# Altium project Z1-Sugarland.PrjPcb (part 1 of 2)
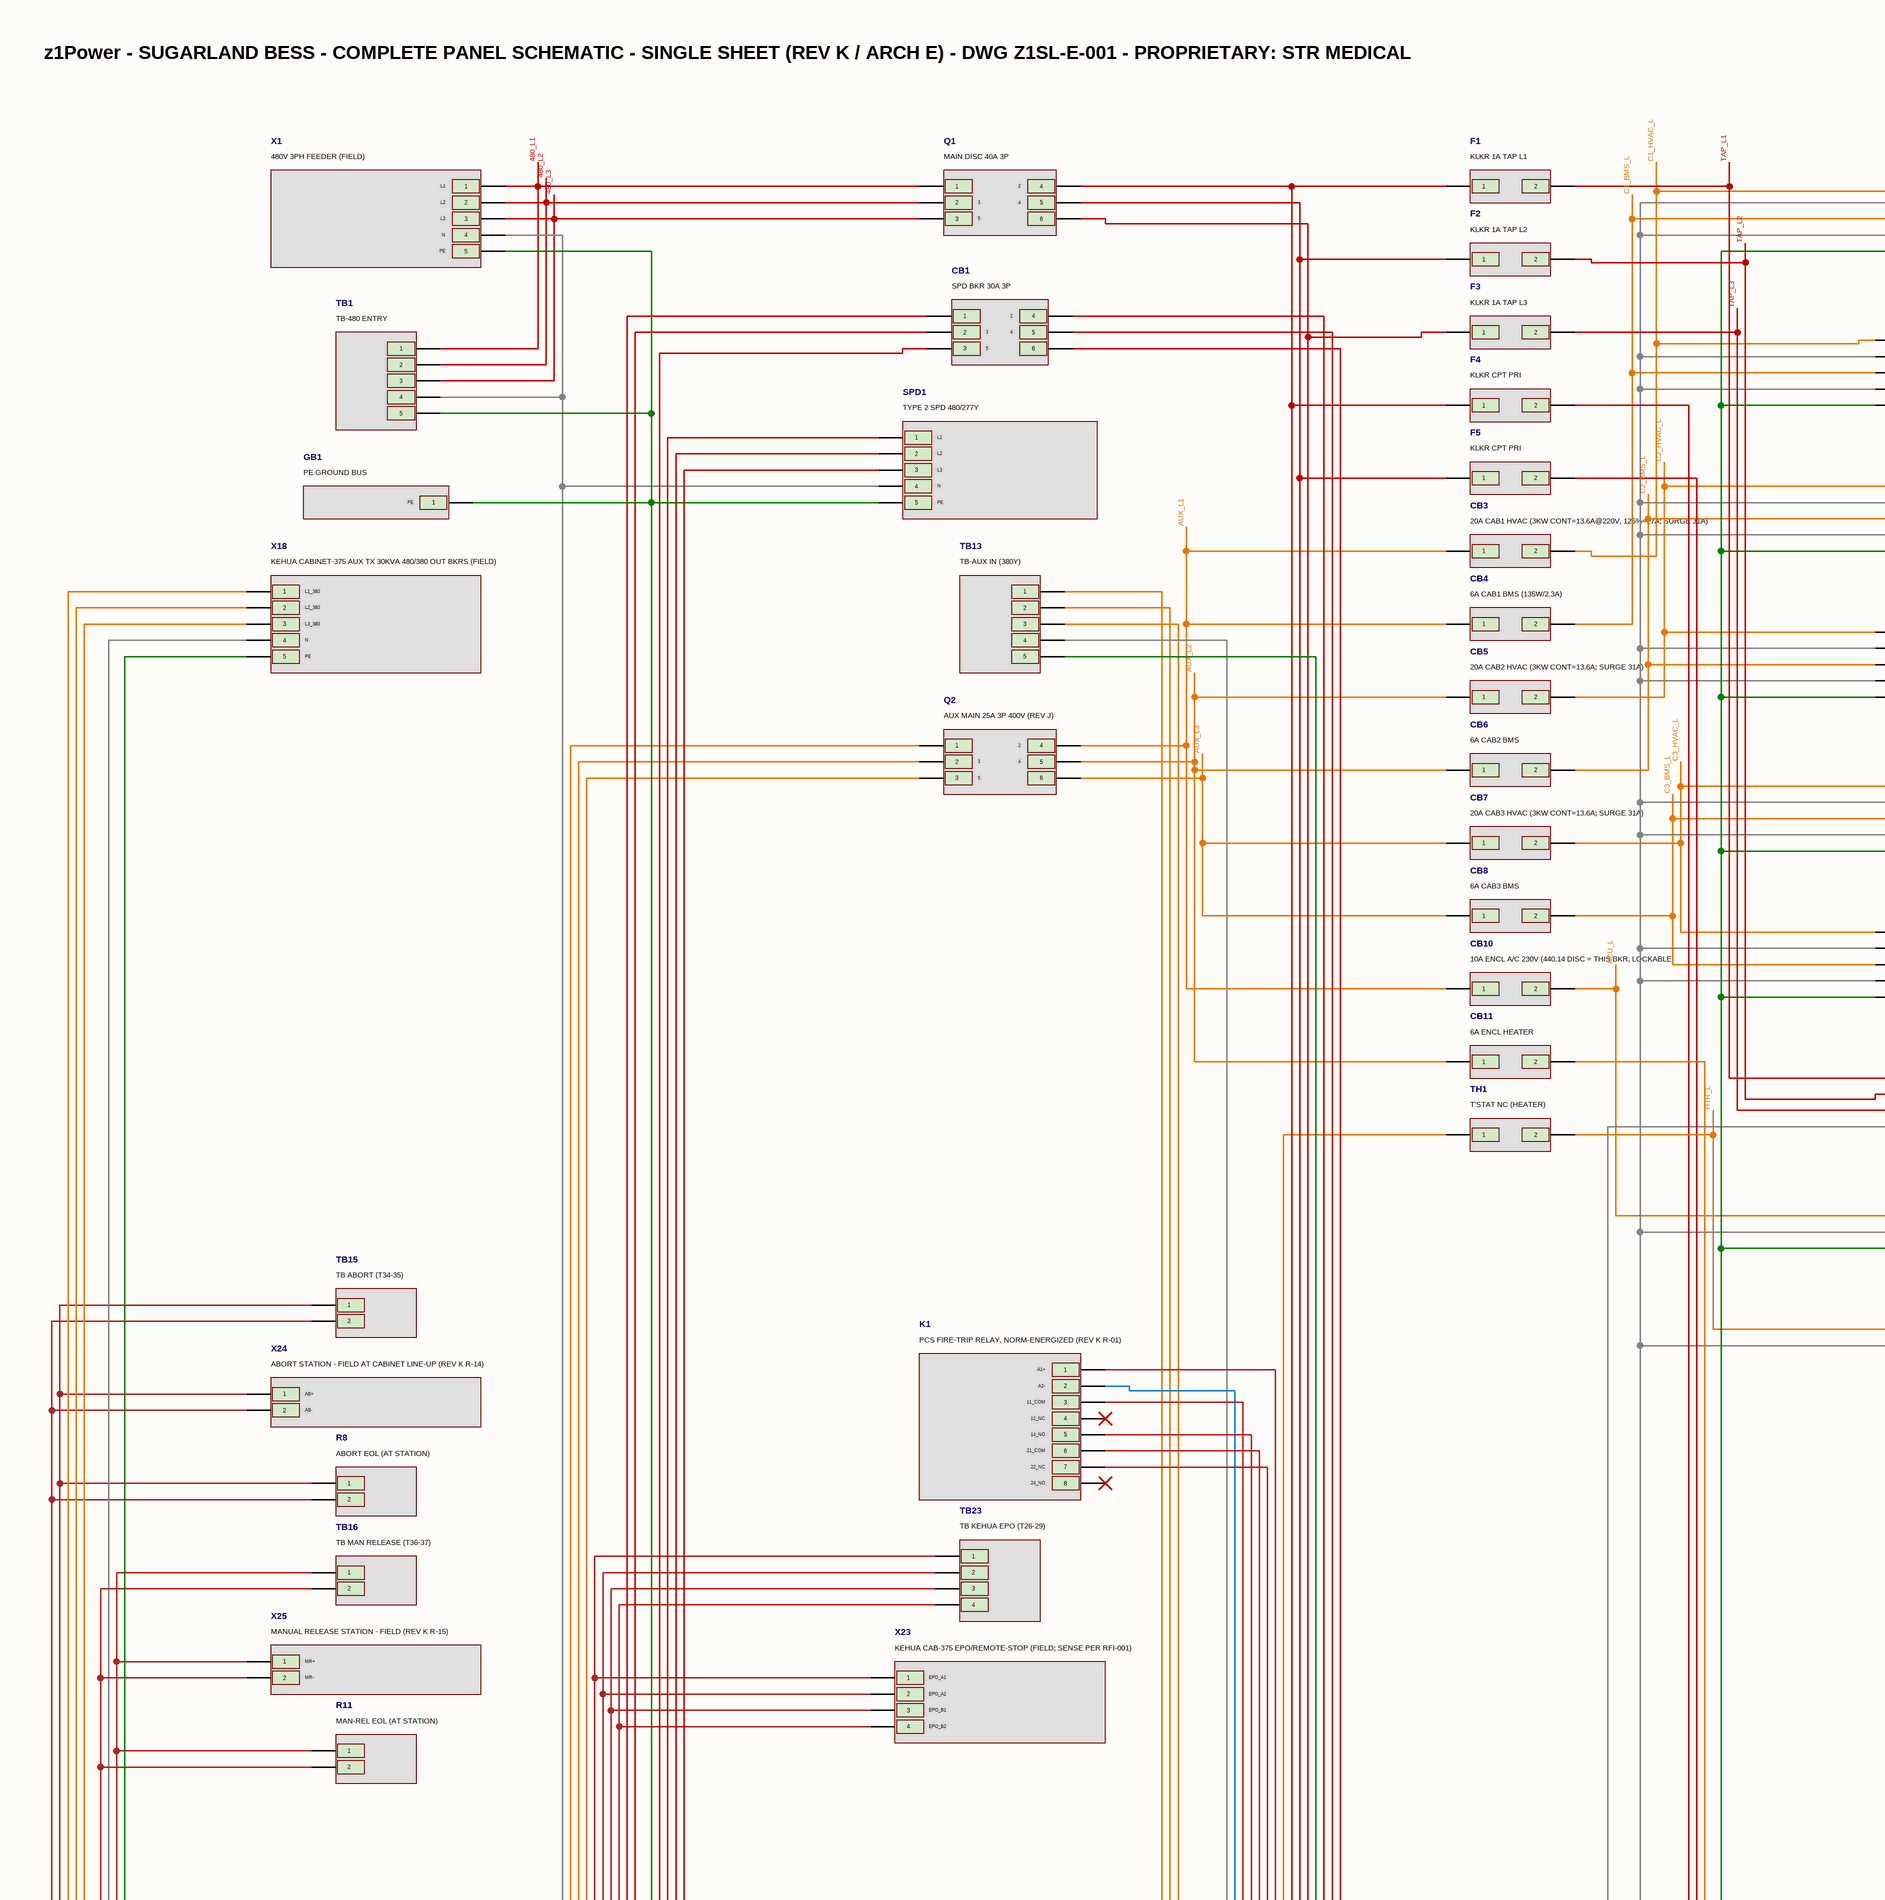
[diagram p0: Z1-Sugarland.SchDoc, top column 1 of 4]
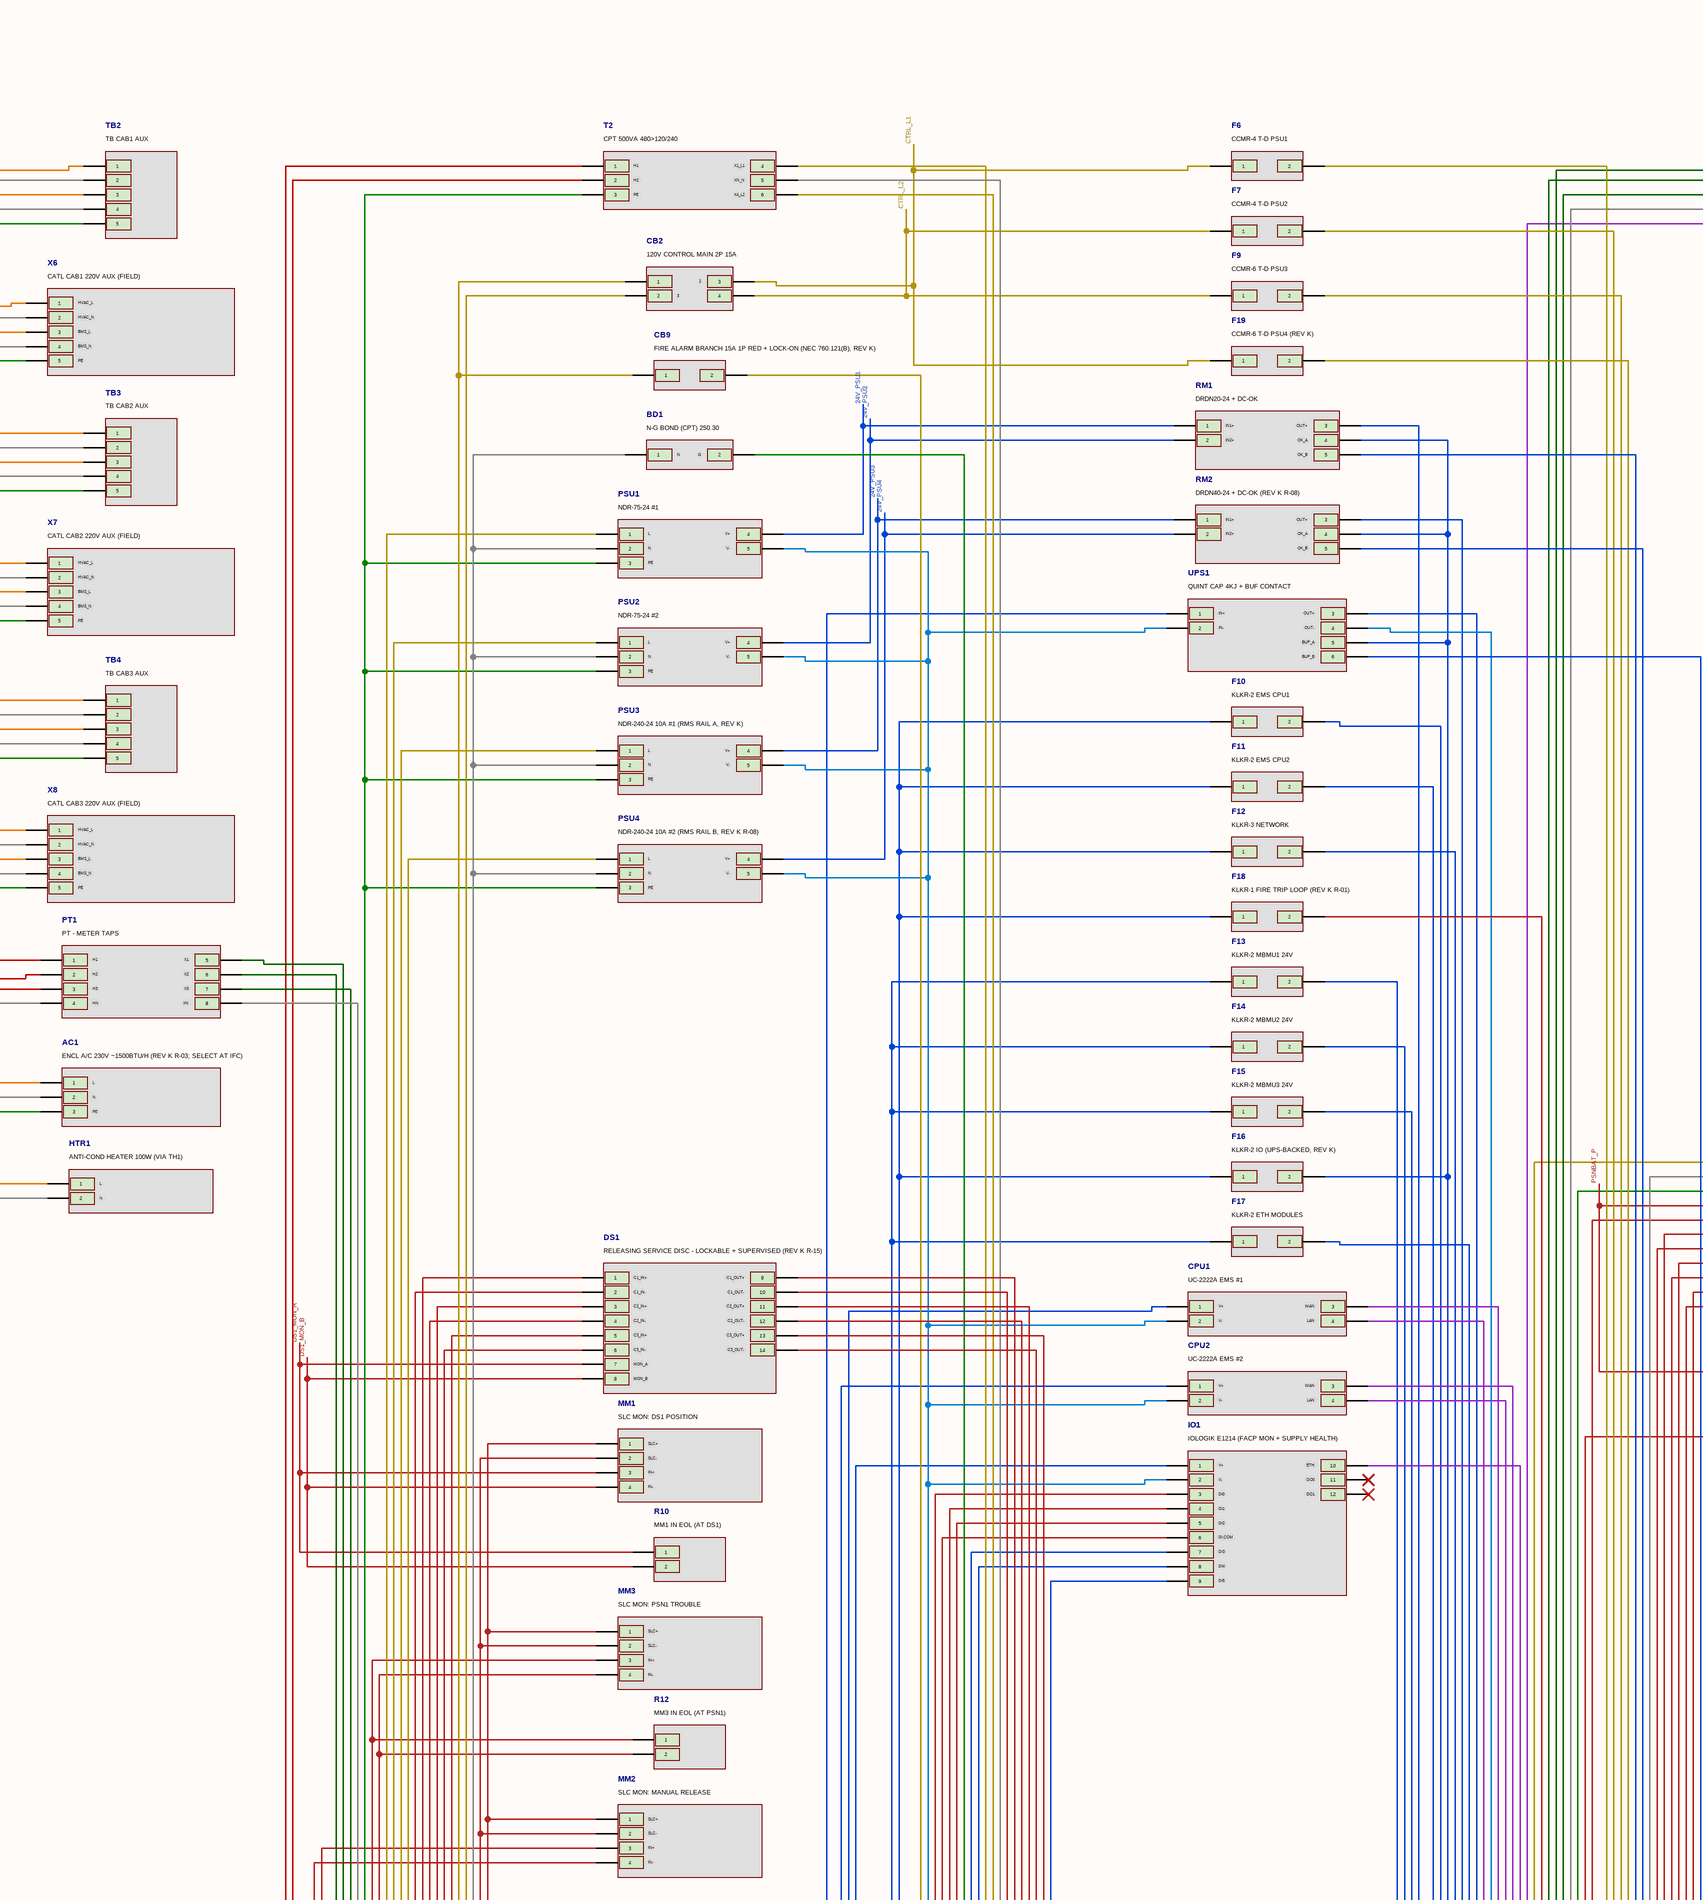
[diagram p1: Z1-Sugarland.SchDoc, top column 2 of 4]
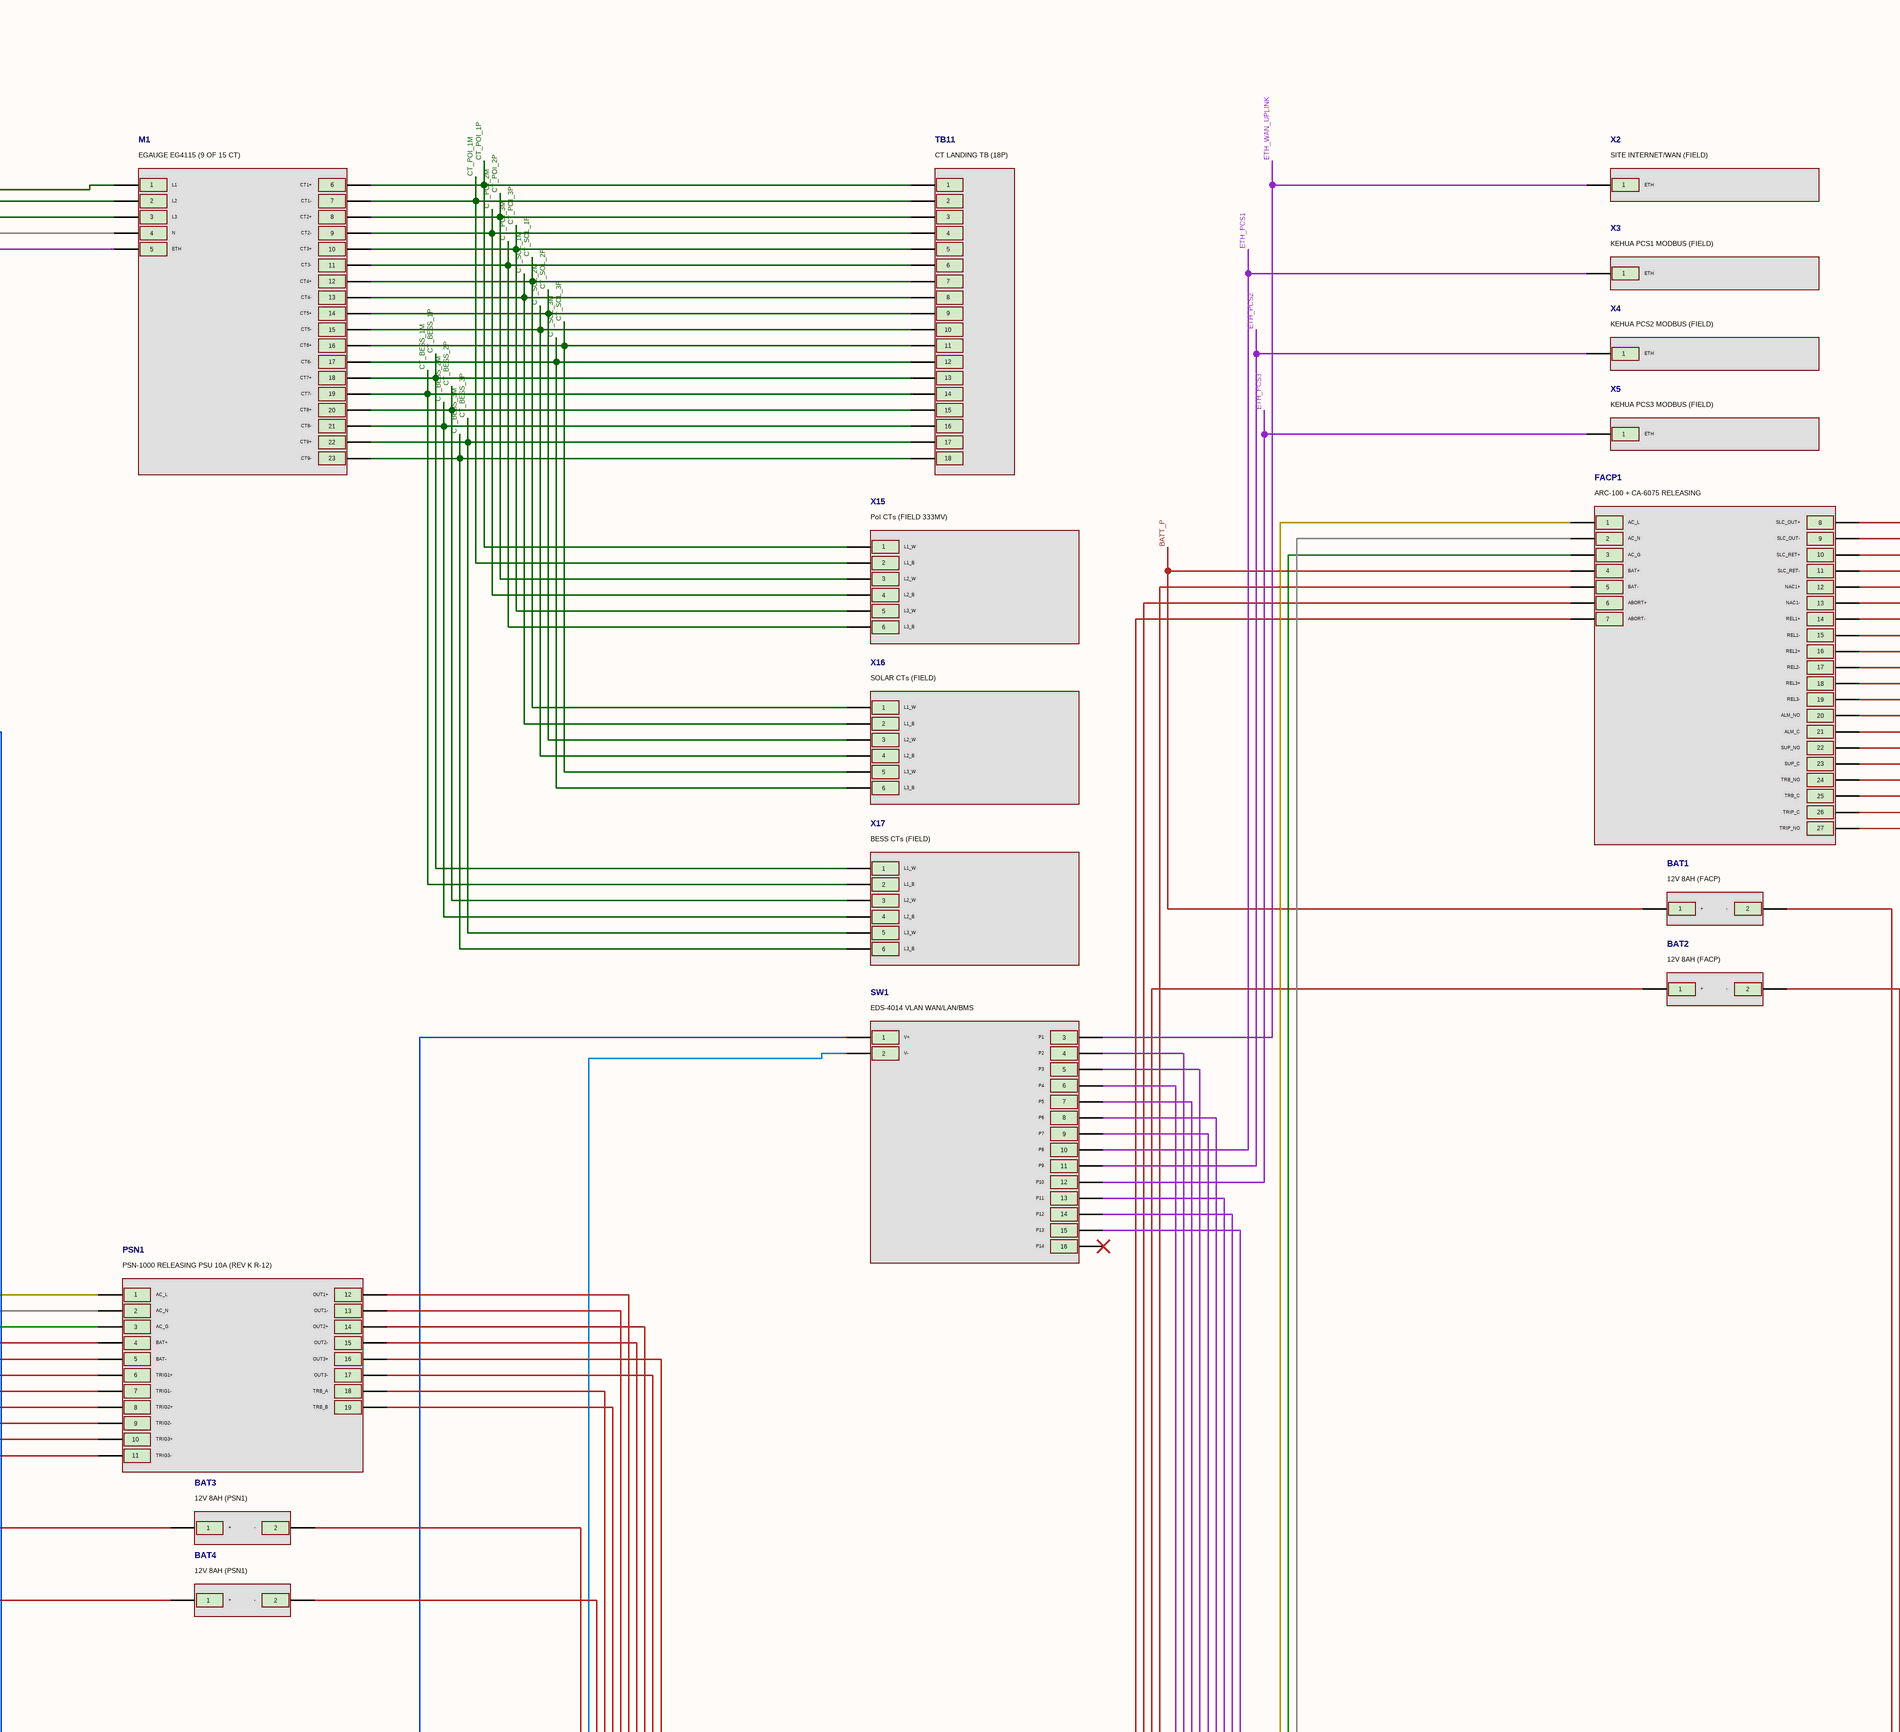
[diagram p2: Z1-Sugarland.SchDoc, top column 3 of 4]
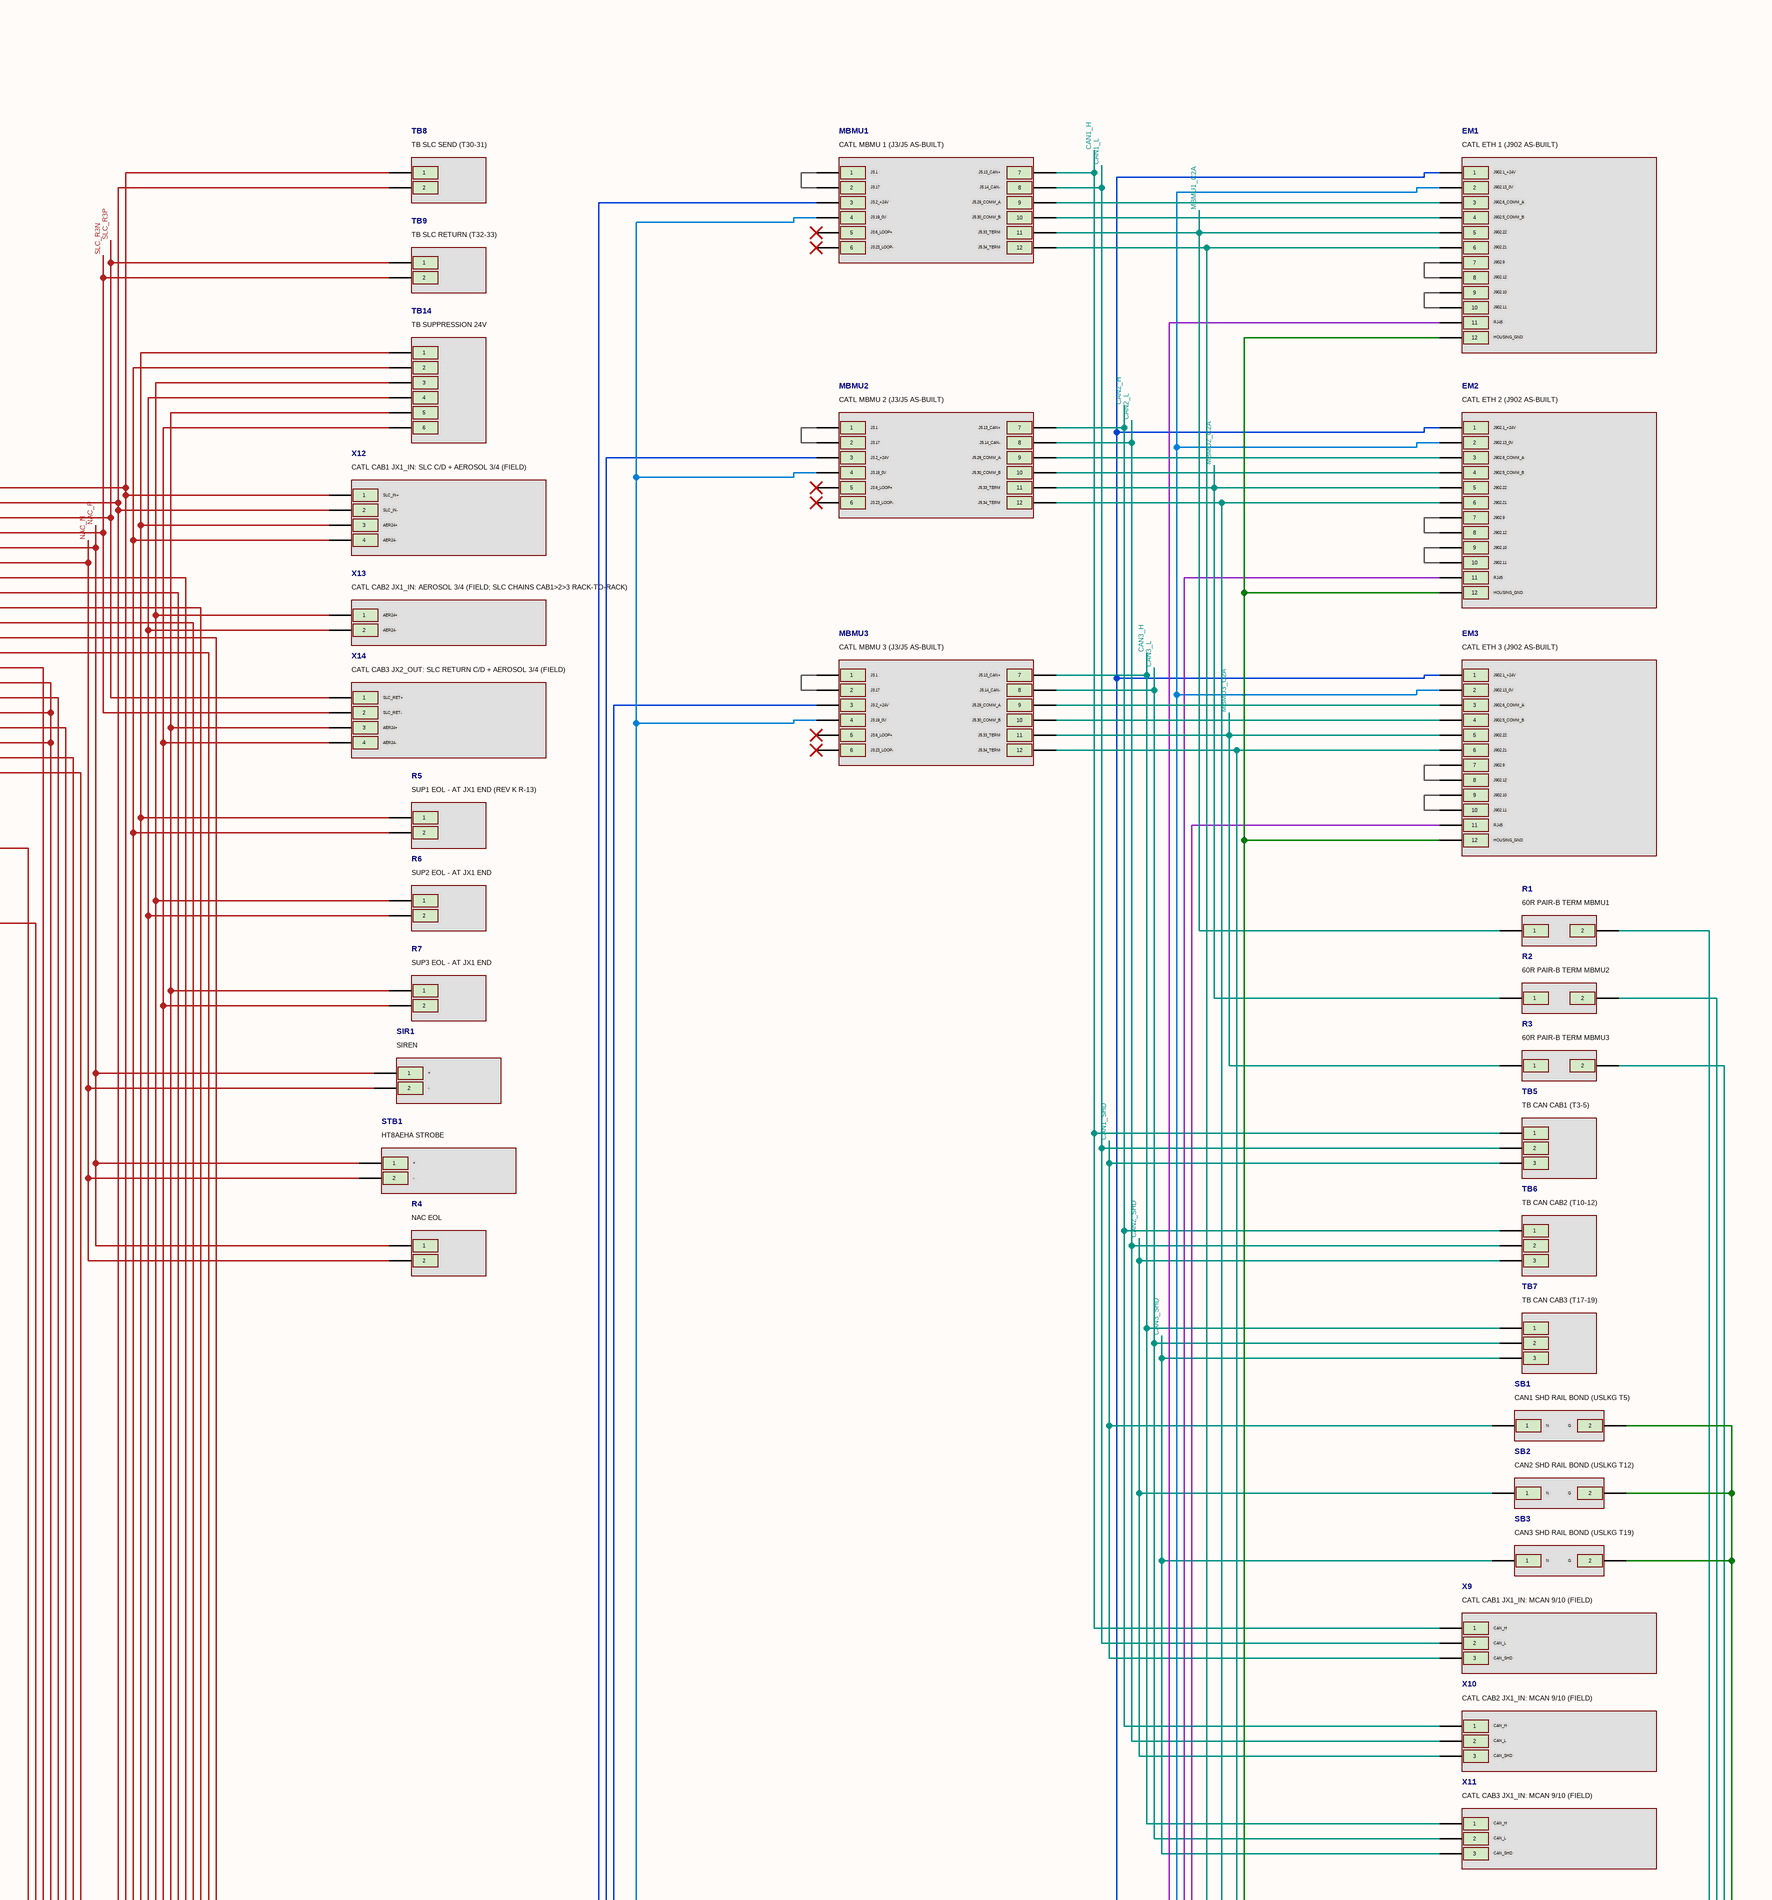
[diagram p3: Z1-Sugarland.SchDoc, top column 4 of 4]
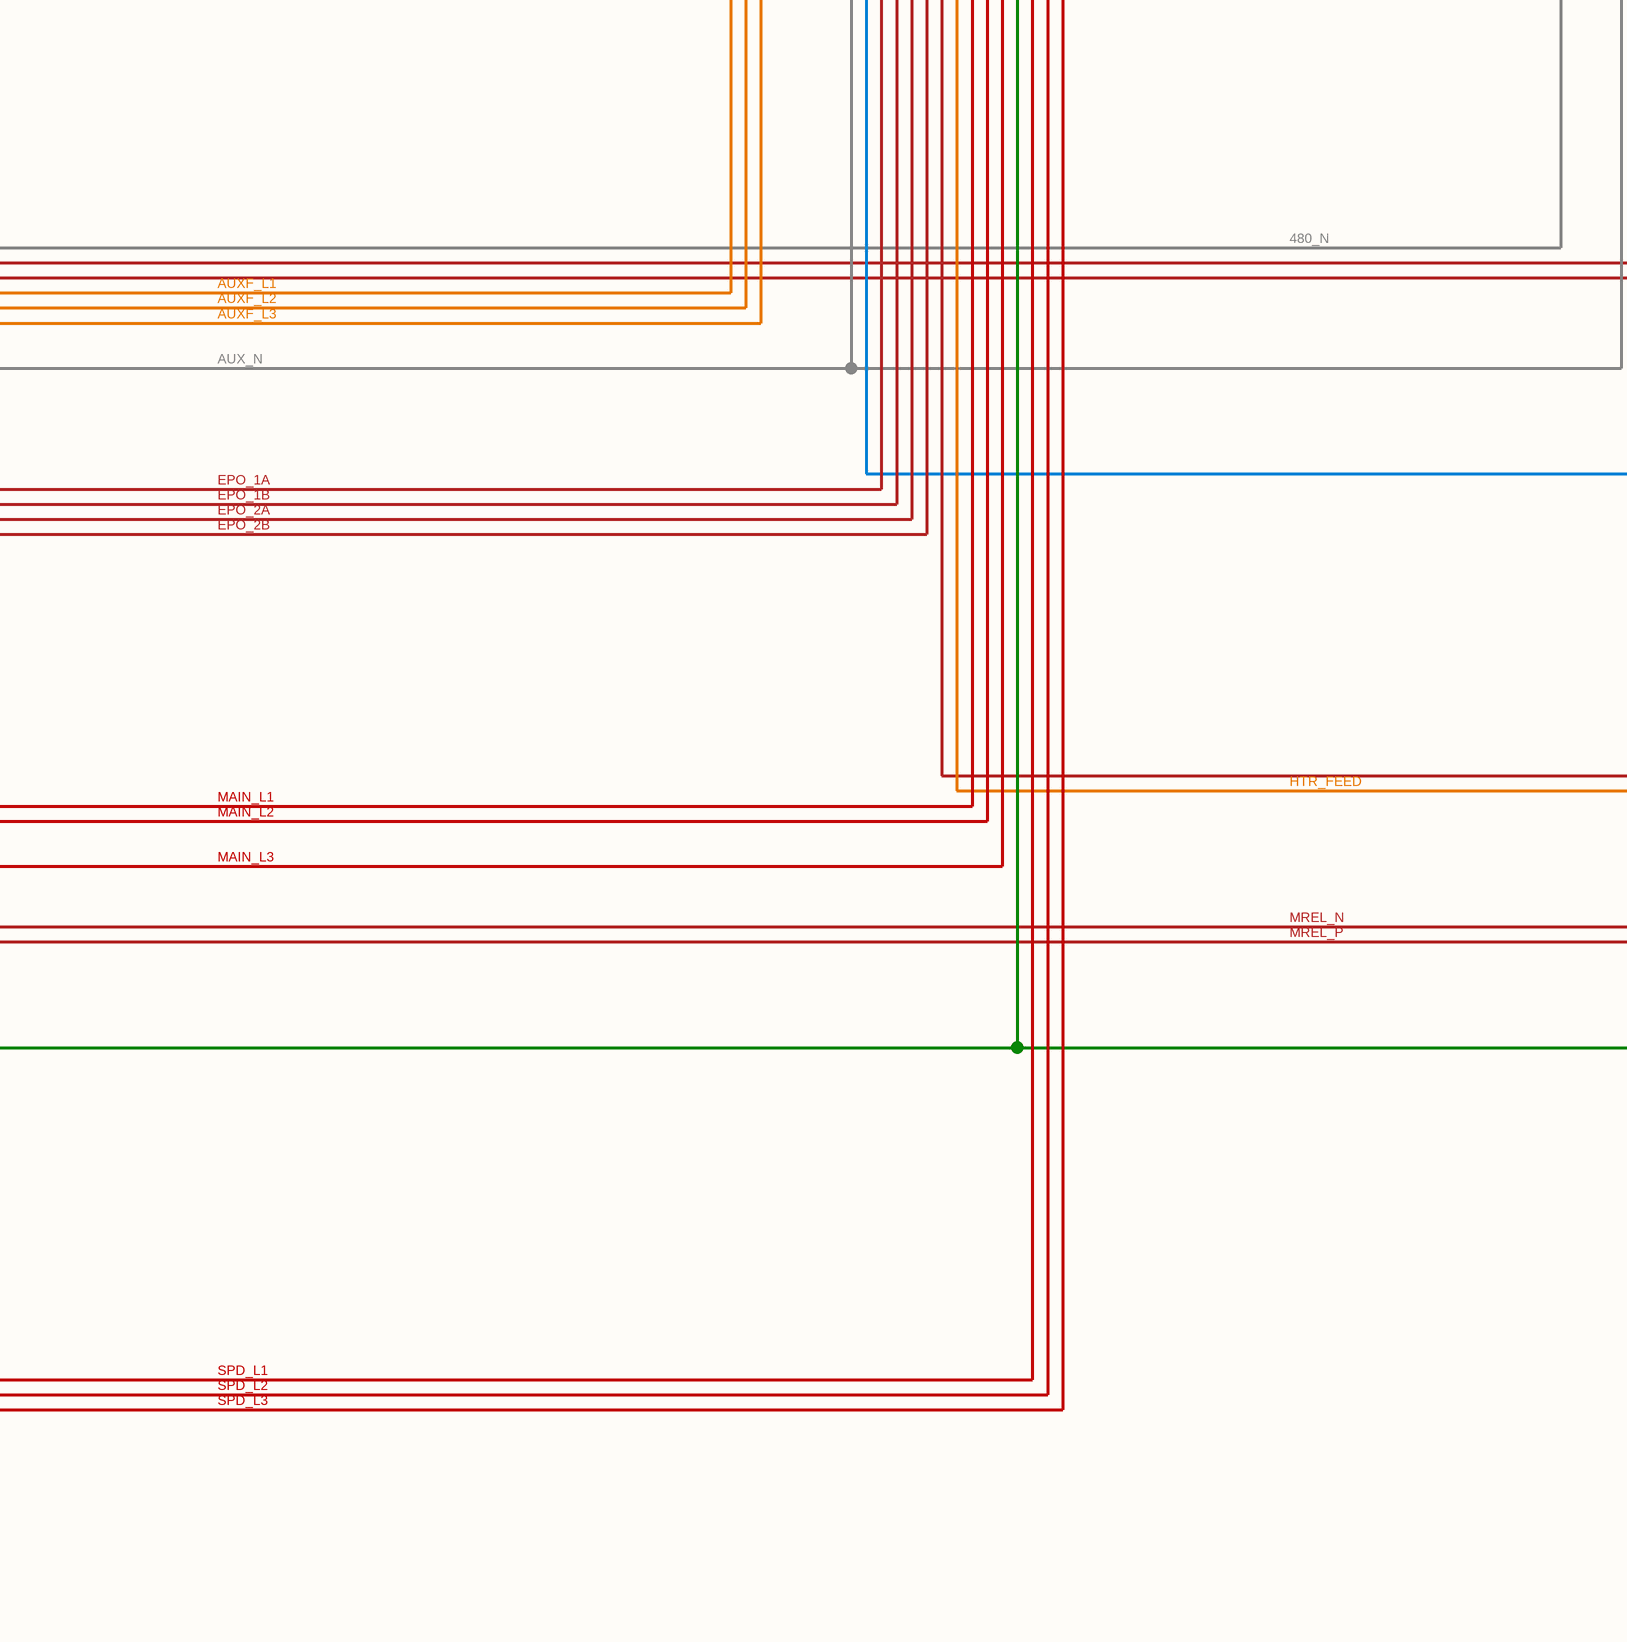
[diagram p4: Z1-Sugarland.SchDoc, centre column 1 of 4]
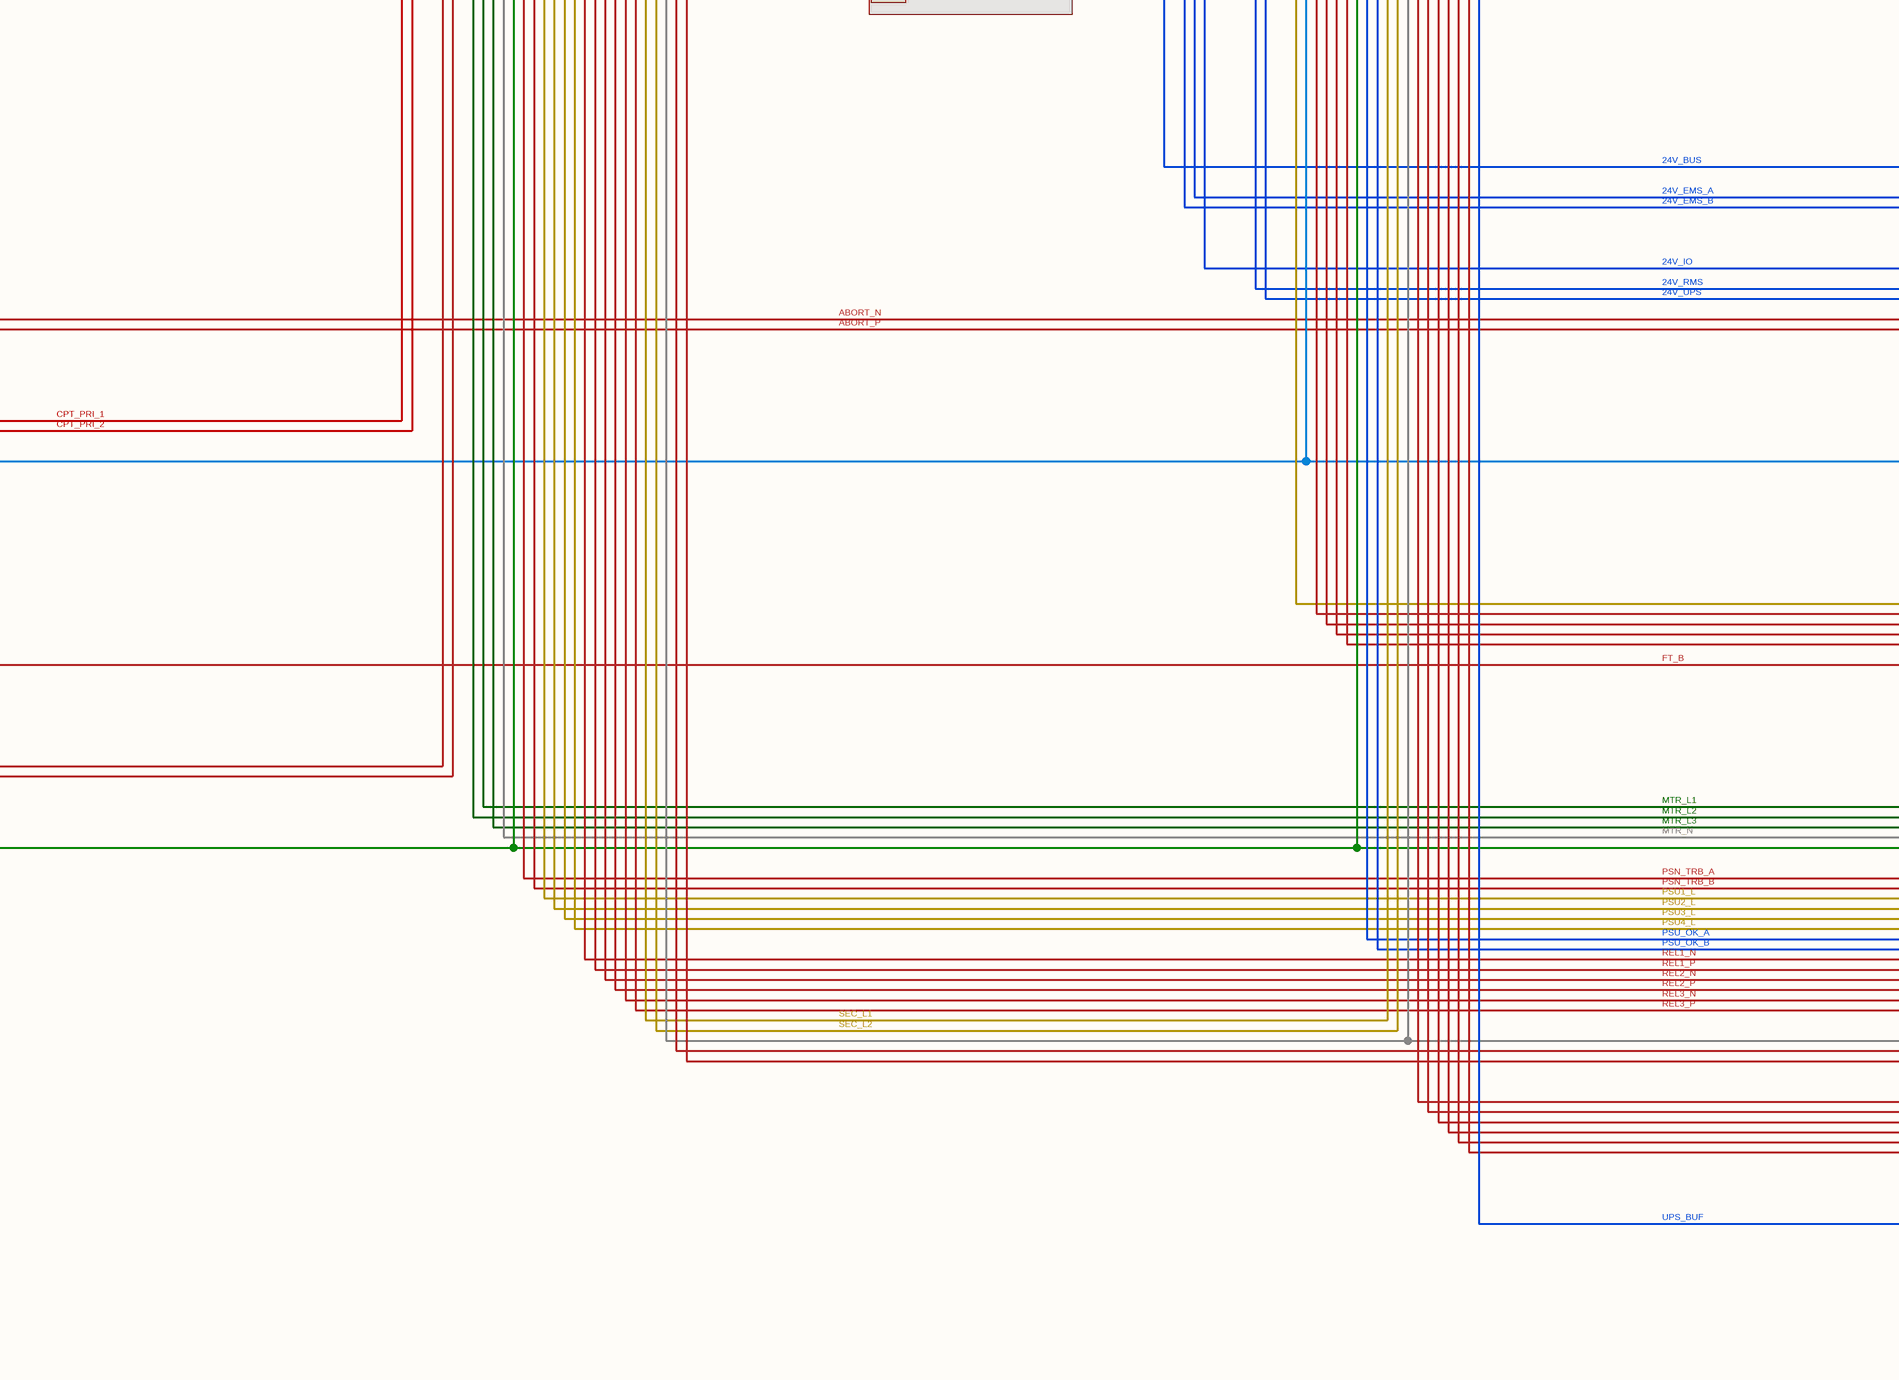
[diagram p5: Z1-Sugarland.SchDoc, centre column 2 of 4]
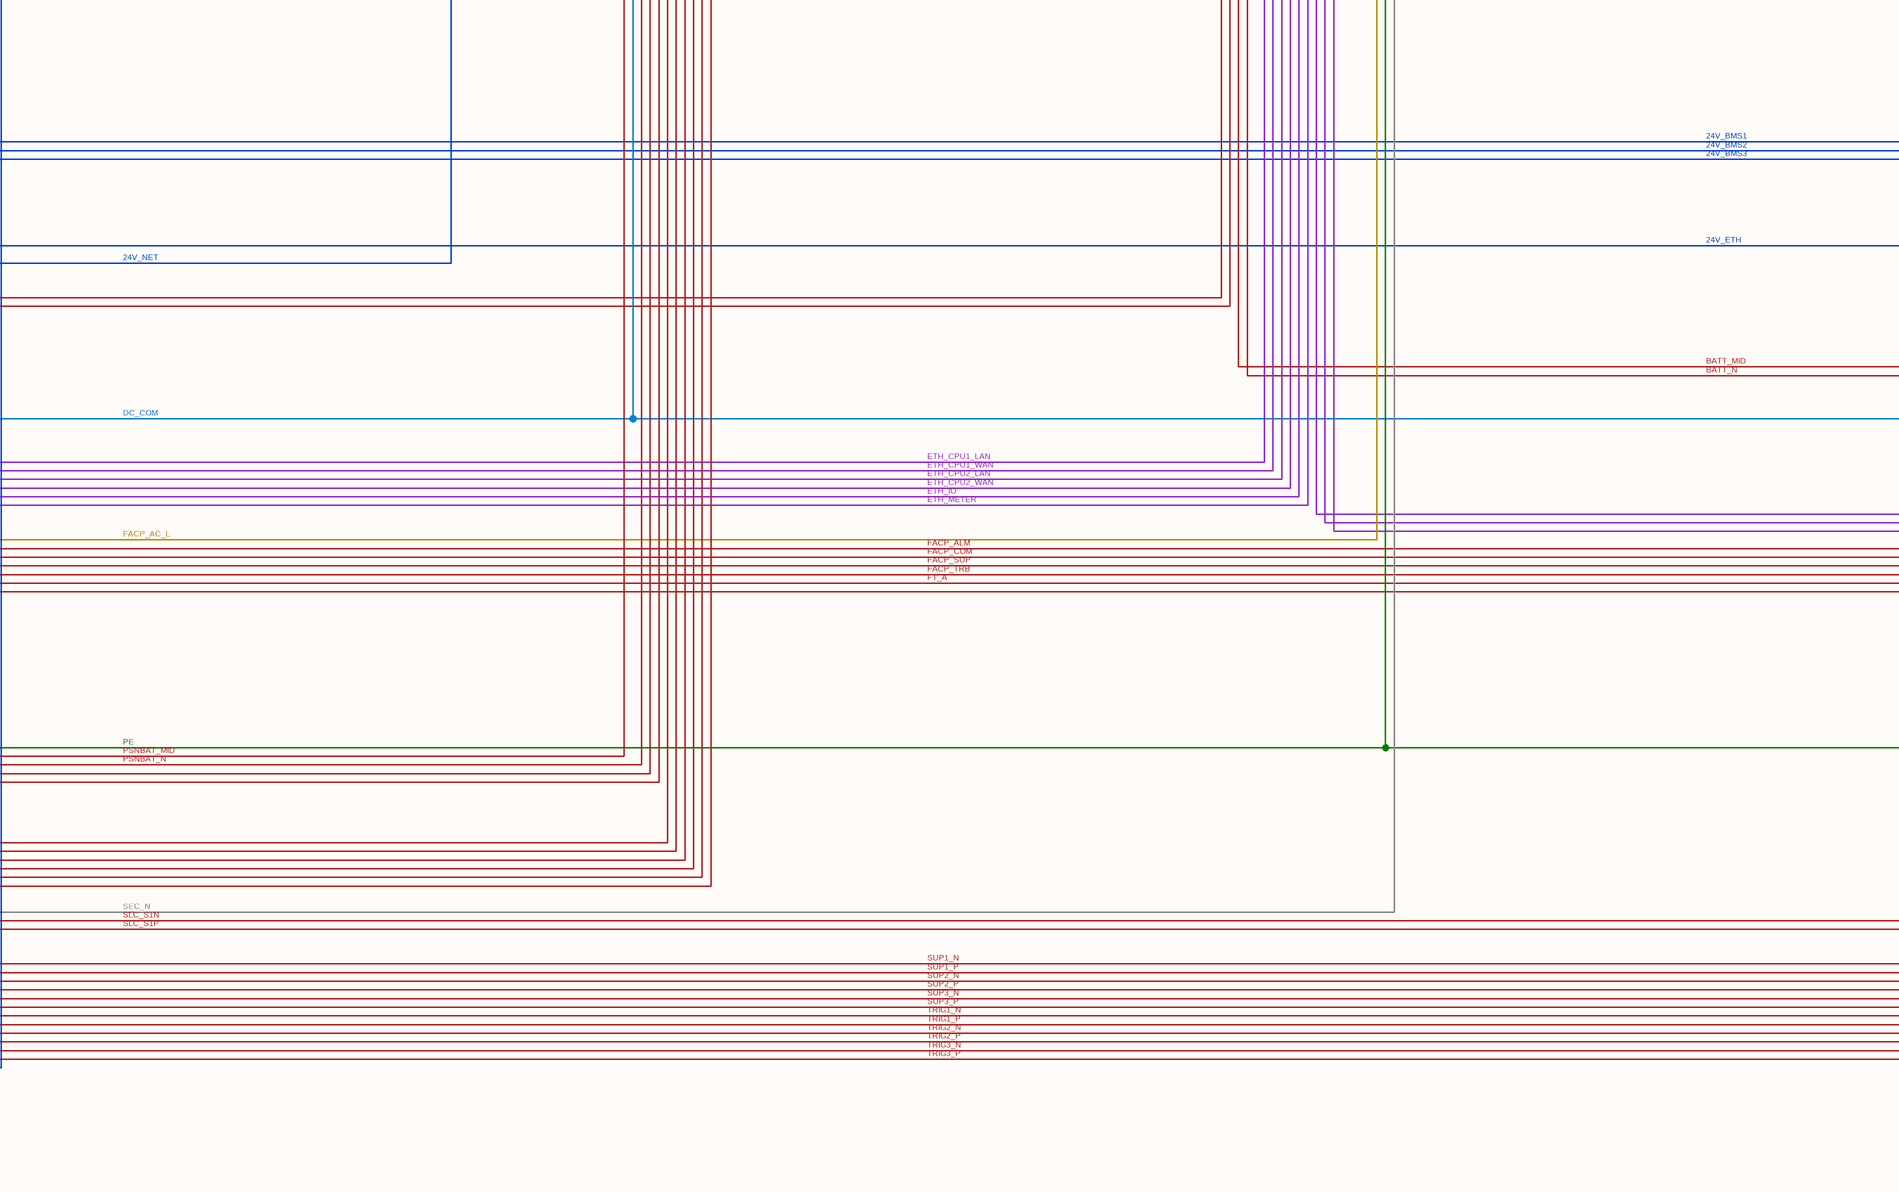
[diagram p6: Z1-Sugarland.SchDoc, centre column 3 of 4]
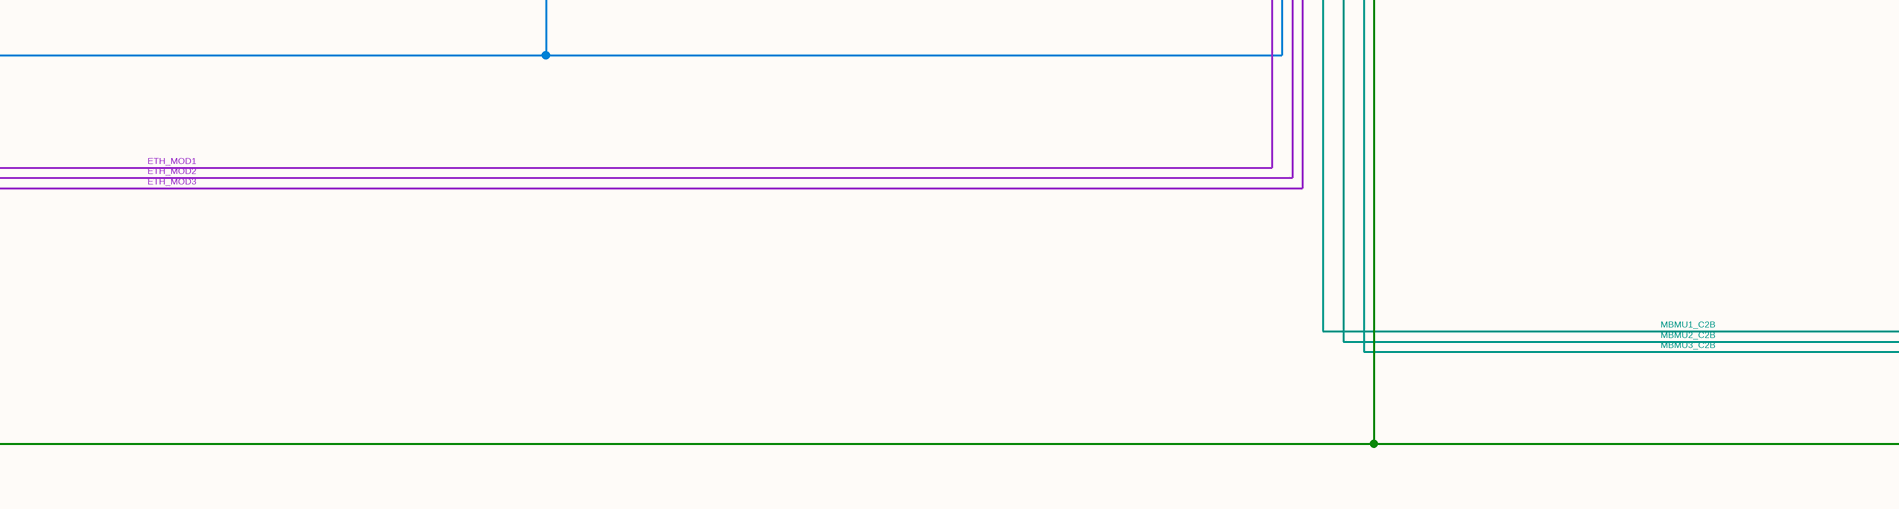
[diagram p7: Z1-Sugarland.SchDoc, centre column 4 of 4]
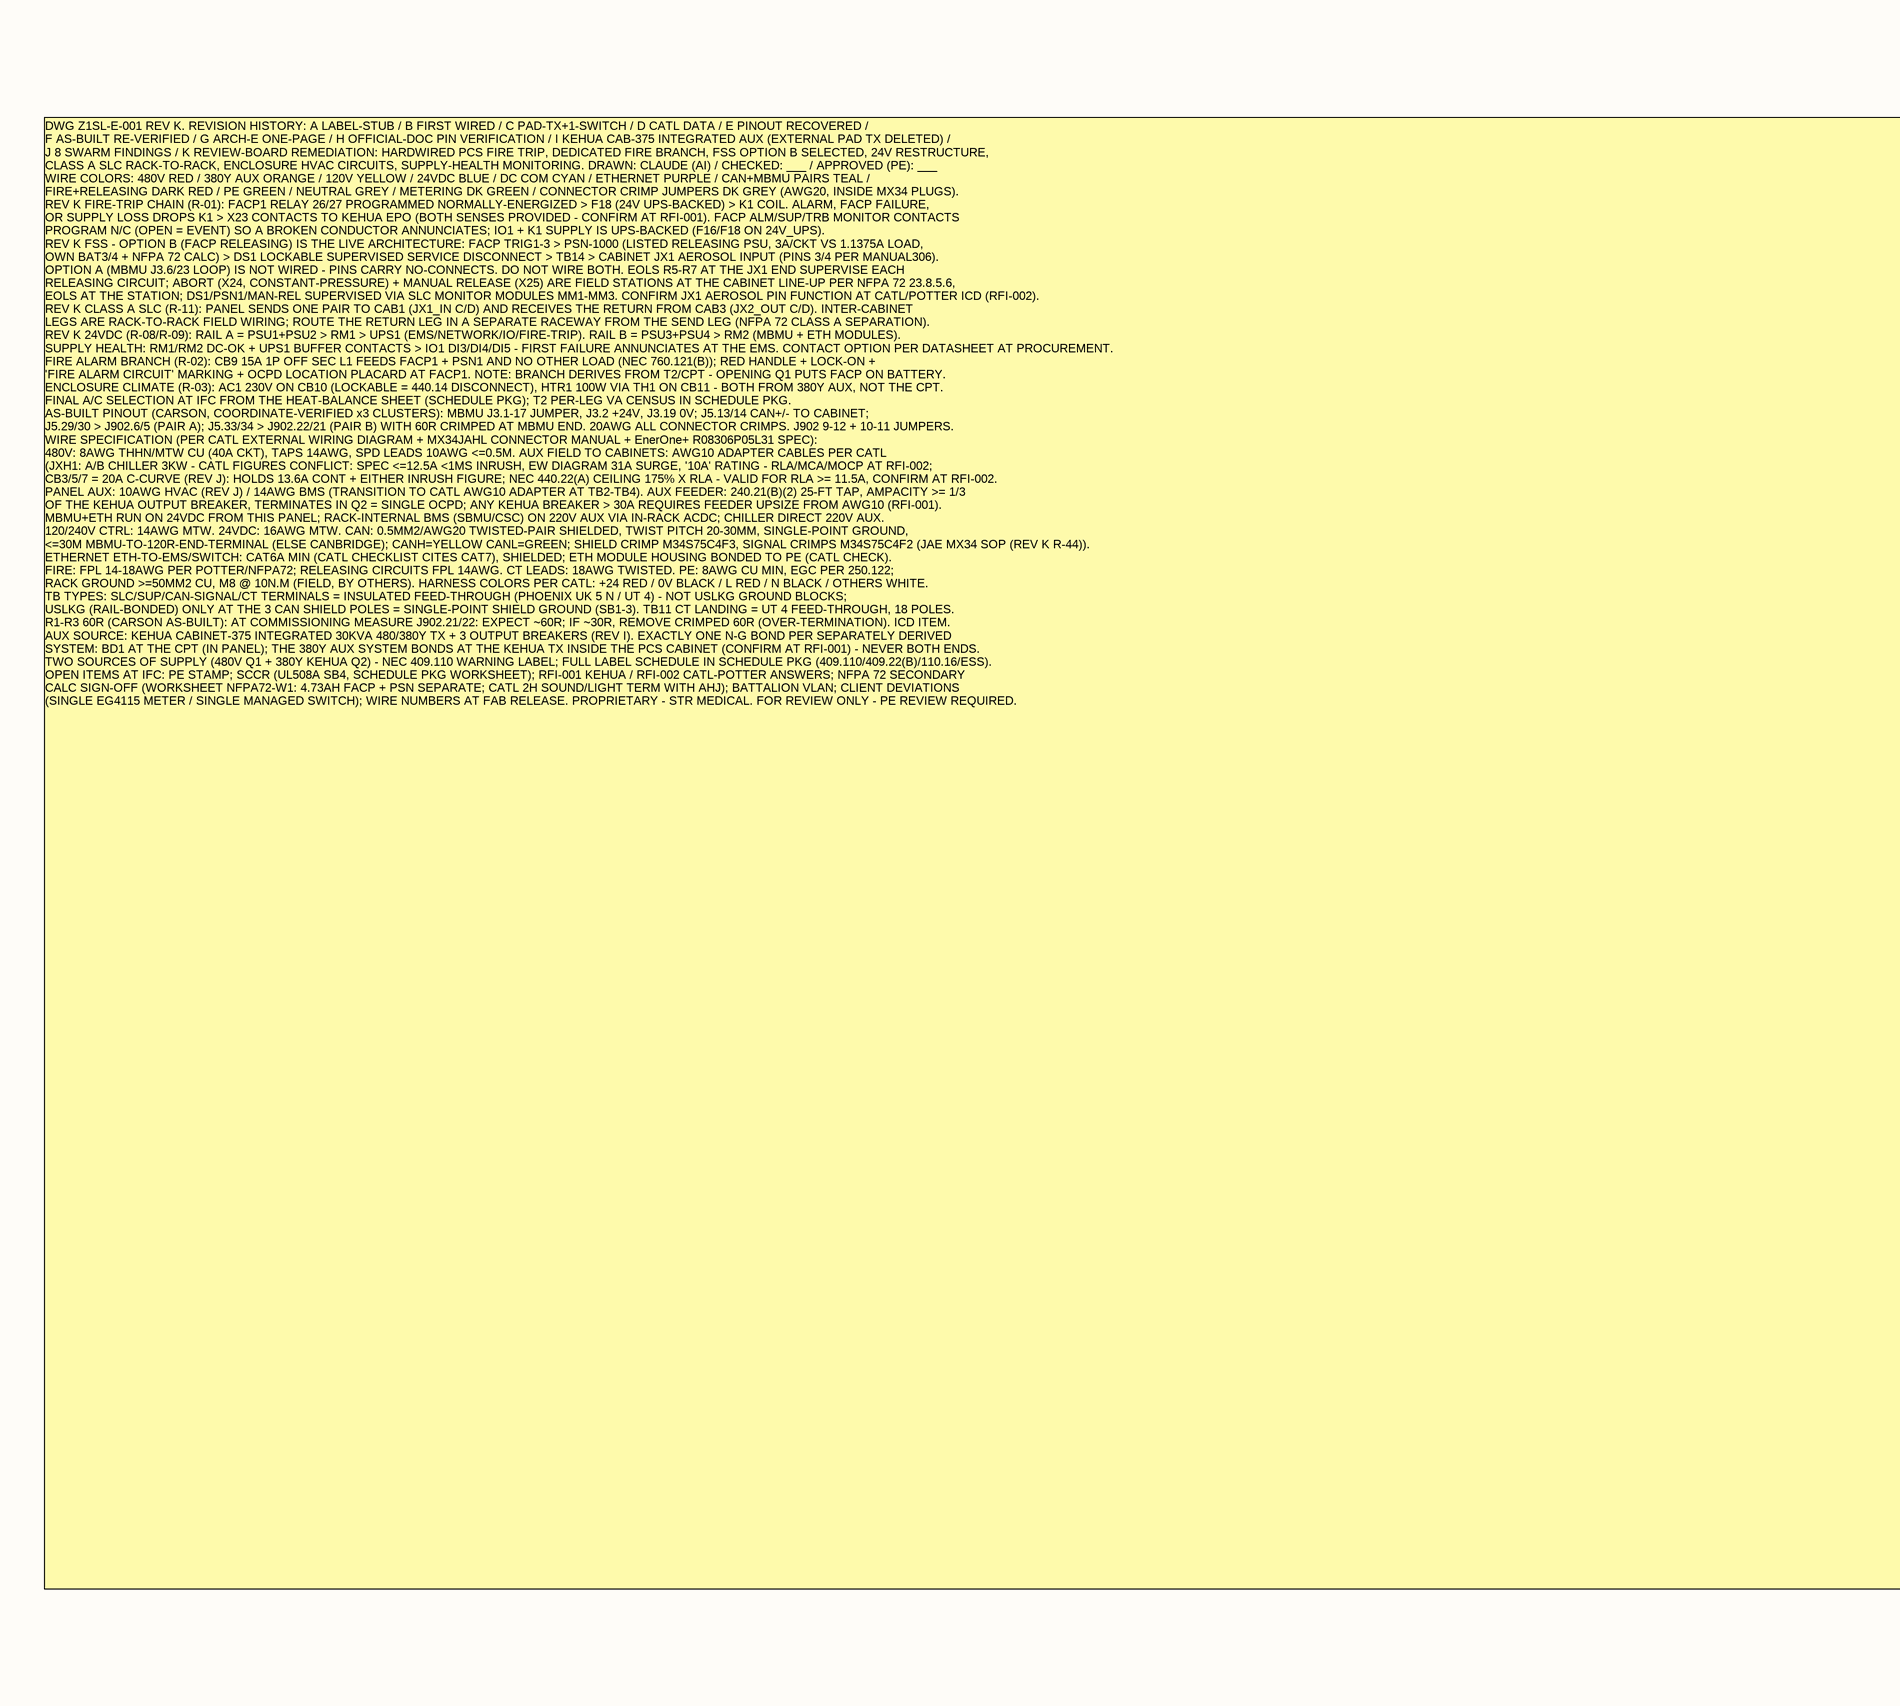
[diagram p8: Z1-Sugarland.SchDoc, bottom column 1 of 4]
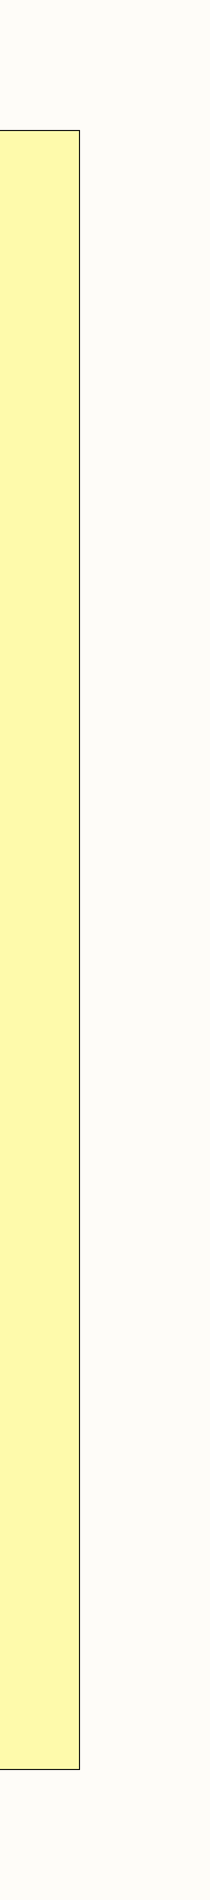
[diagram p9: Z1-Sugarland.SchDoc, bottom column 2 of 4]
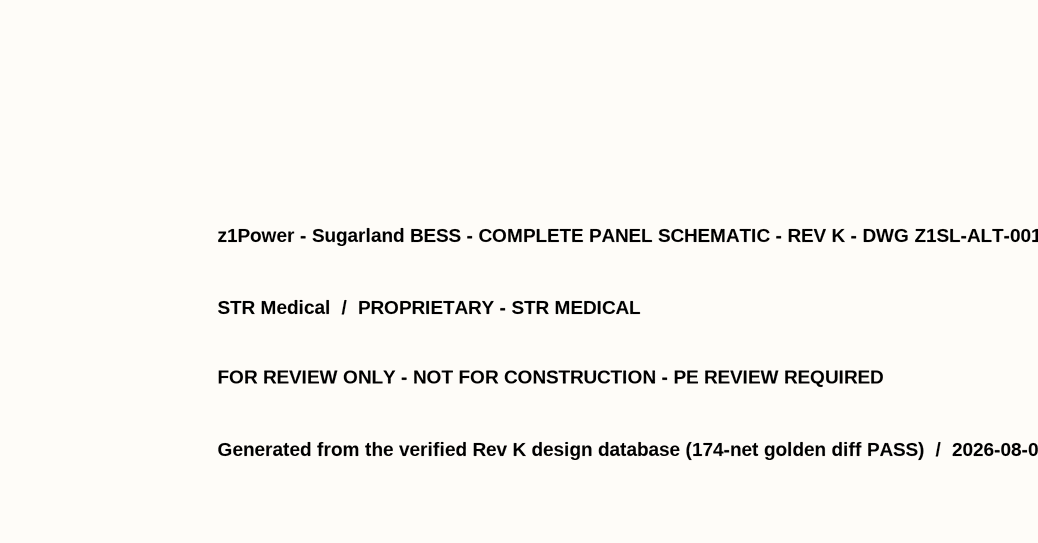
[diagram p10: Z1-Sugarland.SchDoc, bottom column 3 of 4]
2 sheets, 240 parts. Net scope: global (net labels, ports and power ports of the same name join across sheets).
Sheets:
  Z1-Sugarland.SchDoc
  Z1-Sugarland-Simplified.SchDoc

## Sheet Z1-Sugarland.SchDoc
size 1219 x 914 mm

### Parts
(Parts that share a designator on the sheet are numbered #1, #2 ... from top to bottom, then left to right.)
AC1#1  ENCL A/C 230V ~1500BTU/H (REV K R-03; SELECT AT IFC)
BAT1#1  12V 8AH (FACP)
BAT2#1  12V 8AH (FACP)
BAT3#1  12V 8AH (PSN1)
BAT4#1  12V 8AH (PSN1)
BD1#1  N-G BOND (CPT) 250.30
CB1#1  SPD BKR 30A 3P
CB2#1  120V CONTROL MAIN 2P 15A
CB3#1  20A CAB1 HVAC (3KW CONT=13.6A@220V, 125%=17A; SURGE 31A)
CB4#1  6A CAB1 BMS (135W/2.3A)
CB5#1  20A CAB2 HVAC (3KW CONT=13.6A; SURGE 31A)
CB6#1  6A CAB2 BMS
CB7#1  20A CAB3 HVAC (3KW CONT=13.6A; SURGE 31A)
CB8#1  6A CAB3 BMS
CB9#1  FIRE ALARM BRANCH 15A 1P RED + LOCK-ON (NEC 760.121(B), REV K)
CB10#1  10A ENCL A/C 230V (440.14 DISC = THIS BKR, LOCKABLE)
CB11#1  6A ENCL HEATER
CPU1#1  UC-2222A EMS #1
CPU2#1  UC-2222A EMS #2
DS1#1  RELEASING SERVICE DISC - LOCKABLE + SUPERVISED (REV K R-15)
EM1#1  CATL ETH 1 (J902 AS-BUILT)
EM2#1  CATL ETH 2 (J902 AS-BUILT)
EM3#1  CATL ETH 3 (J902 AS-BUILT)
F1#1  KLKR 1A TAP L1
F2#1  KLKR 1A TAP L2
F3#1  KLKR 1A TAP L3
F4#1  KLKR CPT PRI
F5#1  KLKR CPT PRI
F6#1  CCMR-4 T-D PSU1
F7#1  CCMR-4 T-D PSU2
F9#1  CCMR-6 T-D PSU3
F10#1  KLKR-2 EMS CPU1
F11#1  KLKR-2 EMS CPU2
F12#1  KLKR-3 NETWORK
F13#1  KLKR-2 MBMU1 24V
F14#1  KLKR-2 MBMU2 24V
F15#1  KLKR-2 MBMU3 24V
F16#1  KLKR-2 IO (UPS-BACKED, REV K)
F17#1  KLKR-2 ETH MODULES
F18#1  KLKR-1 FIRE TRIP LOOP (REV K R-01)
F19#1  CCMR-6 T-D PSU4 (REV K)
FACP1#1  ARC-100 + CA-6075 RELEASING
GB1#1  PE GROUND BUS
HTR1#1  ANTI-COND HEATER 100W (VIA TH1)
IO1#1  IOLOGIK E1214 (FACP MON + SUPPLY HEALTH)
K1#1  PCS FIRE-TRIP RELAY, NORM-ENERGIZED (REV K R-01)
M1#1  EGAUGE EG4115 (9 OF 15 CT)
MBMU1#1  CATL MBMU 1 (J3/J5 AS-BUILT)
MBMU2#1  CATL MBMU 2 (J3/J5 AS-BUILT)
MBMU3#1  CATL MBMU 3 (J3/J5 AS-BUILT)
MM1#1  SLC MON: DS1 POSITION
MM2#1  SLC MON: MANUAL RELEASE
MM3#1  SLC MON: PSN1 TROUBLE
PSN1#1  PSN-1000 RELEASING PSU 10A (REV K R-12)
PSU1#1  NDR-75-24 #1
PSU2#1  NDR-75-24 #2
PSU3#1  NDR-240-24 10A #1 (RMS RAIL A, REV K)
PSU4#1  NDR-240-24 10A #2 (RMS RAIL B, REV K R-08)
PT1#1  PT - METER TAPS
Q1#1  MAIN DISC 40A 3P
Q2#1  AUX MAIN 25A 3P 400V (REV J)
R1#1  60R PAIR-B TERM MBMU1
R2#1  60R PAIR-B TERM MBMU2
R3#1  60R PAIR-B TERM MBMU3
R4#1  NAC EOL
R5#1  SUP1 EOL - AT JX1 END (REV K R-13)
R6#1  SUP2 EOL - AT JX1 END
R7#1  SUP3 EOL - AT JX1 END
R8#1  ABORT EOL (AT STATION)
R10#1  MM1 IN EOL (AT DS1)
R11#1  MAN-REL EOL (AT STATION)
R12#1  MM3 IN EOL (AT PSN1)
RM1#1  DRDN20-24 + DC-OK
RM2#1  DRDN40-24 + DC-OK (REV K R-08)
SB1#1  CAN1 SHD RAIL BOND (USLKG T5)
SB2#1  CAN2 SHD RAIL BOND (USLKG T12)
SB3#1  CAN3 SHD RAIL BOND (USLKG T19)
SIR1#1  SIREN
SPD1#1  TYPE 2 SPD 480/277Y
STB1#1  HT8AEHA STROBE
SW1#1  EDS-4014 VLAN WAN/LAN/BMS
T2#1  CPT 500VA 480>120/240
TB1#1  TB-480 ENTRY
TB2#1  TB CAB1 AUX
TB3#1  TB CAB2 AUX
TB4#1  TB CAB3 AUX
TB5#1  TB CAN CAB1 (T3-5)
TB6#1  TB CAN CAB2 (T10-12)
TB7#1  TB CAN CAB3 (T17-19)
TB8#1  TB SLC SEND (T30-31)
TB9#1  TB SLC RETURN (T32-33)
TB11#1  CT LANDING TB (18P)
TB13#1  TB-AUX IN (380Y)
TB14#1  TB SUPPRESSION 24V
TB15#1  TB ABORT (T34-35)
TB16#1  TB MAN RELEASE (T36-37)
TB23#1  TB KEHUA EPO (T26-29)
TH1#1  T'STAT NC (HEATER)
UPS1#1  QUINT CAP 4KJ + BUF CONTACT
X1#1  480V 3PH FEEDER (FIELD)
X2#1  SITE INTERNET/WAN (FIELD)
X3#1  KEHUA PCS1 MODBUS (FIELD)
X4#1  KEHUA PCS2 MODBUS (FIELD)
X5#1  KEHUA PCS3 MODBUS (FIELD)
X6#1  CATL CAB1 220V AUX (FIELD)
X7#1  CATL CAB2 220V AUX (FIELD)
X8#1  CATL CAB3 220V AUX (FIELD)
X9#1  CATL CAB1 JX1_IN: MCAN 9/10 (FIELD)
X10#1  CATL CAB2 JX1_IN: MCAN 9/10 (FIELD)
X11#1  CATL CAB3 JX1_IN: MCAN 9/10 (FIELD)
X12#1  CATL CAB1 JX1_IN: SLC C/D + AEROSOL 3/4 (FIELD)
X13#1  CATL CAB2 JX1_IN: AEROSOL 3/4 (FIELD; SLC CHAINS CAB1>2>3 RACK-TO-RACK)
X14#1  CATL CAB3 JX2_OUT: SLC RETURN C/D + AEROSOL 3/4 (FIELD)
X15#1  PoI CTs (FIELD 333MV)
X16#1  SOLAR CTs (FIELD)
X17#1  BESS CTs (FIELD)
X18#1  KEHUA CABINET-375 AUX TX 30KVA 480/380 OUT BKRS (FIELD)
X23#1  KEHUA CAB-375 EPO/REMOTE-STOP (FIELD; SENSE PER RFI-001)
X24#1  ABORT STATION - FIELD AT CABINET LINE-UP (REV K R-14)
X25#1  MANUAL RELEASE STATION - FIELD (REV K R-15)

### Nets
24V_ETH: EM1#1.1(J902.1_+24V) EM2#1.1(J902.1_+24V) EM3#1.1(J902.1_+24V) F17#1.2
24V_RMS: F13#1.1 F14#1.1 F15#1.1 F17#1.1 RM2#1.3(OUT+)
24V_UPS: F10#1.1 F11#1.1 F12#1.1 F16#1.1 F18#1.1 UPS1#1.3(OUT+)
DC_COM: CPU1#1.2(V-) CPU2#1.2(V-) EM1#1.2(J902.13_0V) EM2#1.2(J902.13_0V) EM3#1.2(J902.13_0V) IO1#1.2(V-) K1#1.2(A2-) MBMU1#1.4(J3.19_0V) MBMU2#1.4(J3.19_0V) MBMU3#1.4(J3.19_0V) PSU1#1.5(V-) PSU2#1.5(V-) PSU3#1.5(V-) PSU4#1.5(V-) SW1#1.2(V-) UPS1#1.2(IN-) UPS1#1.4(OUT-)
PE: AC1#1.3(PE) BD1#1.2(G) EM1#1.12(HOUSING_GND) EM2#1.12(HOUSING_GND) EM3#1.12(HOUSING_GND) FACP1#1.3(AC_G) GB1#1.1(PE) PSN1#1.3(AC_G) PSU1#1.3(PE) PSU2#1.3(PE) PSU3#1.3(PE) PSU4#1.3(PE) SB1#1.2(G) SB2#1.2(G) SB3#1.2(G) SPD1#1.5(PE) T2#1.3(PE) TB1#1.5 TB2#1.5 TB3#1.5 TB4#1.5 TB13#1.5 X1#1.5(PE) X6#1.5(PE) X7#1.5(PE) X8#1.5(PE) X18#1.5(PE)
24V_BMS1: F13#1.2 MBMU1#1.3(J3.2_+24V)
24V_BMS2: F14#1.2 MBMU2#1.3(J3.2_+24V)
24V_BMS3: F15#1.2 MBMU3#1.3(J3.2_+24V)
24V_BUS: RM1#1.3(OUT+) UPS1#1.1(IN+)
24V_EMS_A: CPU1#1.1(V+) F10#1.2
24V_EMS_B: CPU2#1.1(V+) F11#1.2
24V_IO: F16#1.2 IO1#1.1(V+) RM1#1.4(OK_A) RM2#1.4(OK_A) UPS1#1.5(BUF_A)
24V_NET: F12#1.2 SW1#1.1(V+)
24V_PSU1: PSU1#1.4(V+) RM1#1.1(IN1+)
24V_PSU2: PSU2#1.4(V+) RM1#1.2(IN2+)
24V_PSU3: PSU3#1.4(V+) RM2#1.1(IN1+)
24V_PSU4: PSU4#1.4(V+) RM2#1.2(IN2+)
480_L1: Q1#1.1 TB1#1.1 X1#1.1(L1)
480_L2: Q1#1.2 TB1#1.2 X1#1.2(L2)
480_L3: Q1#1.3 TB1#1.3 X1#1.3(L3)
480_N: PT1#1.4(HN) SPD1#1.4(N) TB1#1.4 X1#1.4(N)
ABORT_N: FACP1#1.7(ABORT-) R8#1.2 TB15#1.2 X24#1.2(AB-)
ABORT_P: FACP1#1.6(ABORT+) R8#1.1 TB15#1.1 X24#1.1(AB+)
ACU_L: AC1#1.1(L) CB10#1.2
AUX_L1: CB3#1.1 CB4#1.1 CB10#1.1 Q2#1.4
AUX_L2: CB5#1.1 CB6#1.1 CB11#1.1 Q2#1.5
AUX_L3: CB7#1.1 CB8#1.1 Q2#1.6
AUX_N: AC1#1.2(N) HTR1#1.2(N) TB2#1.2 TB2#1.4 TB3#1.2 TB3#1.4 TB4#1.2 TB4#1.4 TB13#1.4 X6#1.2(HVAC_N) X6#1.4(BMS_N) X7#1.2(HVAC_N) X7#1.4(BMS_N) X8#1.2(HVAC_N) X8#1.4(BMS_N) X18#1.4(N)
AUXF_L1: Q2#1.1 TB13#1.1 X18#1.1(L1_380)
AUXF_L2: Q2#1.2 TB13#1.2 X18#1.2(L2_380)
AUXF_L3: Q2#1.3 TB13#1.3 X18#1.3(L3_380)
BATT_MID: BAT1#1.2(-) BAT2#1.1(+)
BATT_N: BAT2#1.2(-) FACP1#1.5(BAT-)
BATT_P: BAT1#1.1(+) FACP1#1.4(BAT+)
C1_BMS_L: CB4#1.2 TB2#1.3 X6#1.3(BMS_L)
C1_HVAC_L: CB3#1.2 TB2#1.1 X6#1.1(HVAC_L)
C2_BMS_L: CB6#1.2 TB3#1.3 X7#1.3(BMS_L)
C2_HVAC_L: CB5#1.2 TB3#1.1 X7#1.1(HVAC_L)
C3_BMS_L: CB8#1.2 TB4#1.3 X8#1.3(BMS_L)
C3_HVAC_L: CB7#1.2 TB4#1.1 X8#1.1(HVAC_L)
CAN1_H: MBMU1#1.7(J5.13_CAN+) TB5#1.1 X9#1.1(CAN_H)
CAN1_L: MBMU1#1.8(J5.14_CAN-) TB5#1.2 X9#1.2(CAN_L)
CAN1_SHD: SB1#1.1(N) TB5#1.3 X9#1.3(CAN_SHD)
CAN2_H: MBMU2#1.7(J5.13_CAN+) TB6#1.1 X10#1.1(CAN_H)
CAN2_L: MBMU2#1.8(J5.14_CAN-) TB6#1.2 X10#1.2(CAN_L)
CAN2_SHD: SB2#1.1(N) TB6#1.3 X10#1.3(CAN_SHD)
CAN3_H: MBMU3#1.7(J5.13_CAN+) TB7#1.1 X11#1.1(CAN_H)
CAN3_L: MBMU3#1.8(J5.14_CAN-) TB7#1.2 X11#1.2(CAN_L)
CAN3_SHD: SB3#1.1(N) TB7#1.3 X11#1.3(CAN_SHD)
CPT_PRI_1: F4#1.2 T2#1.1(H1)
CPT_PRI_2: F5#1.2 T2#1.2(H2)
CT_BESS_1M: M1#1.19(CT7-) TB11#1.14 X17#1.2(L1_B)
CT_BESS_1P: M1#1.18(CT7+) TB11#1.13 X17#1.1(L1_W)
CT_BESS_2M: M1#1.21(CT8-) TB11#1.16 X17#1.4(L2_B)
CT_BESS_2P: M1#1.20(CT8+) TB11#1.15 X17#1.3(L2_W)
CT_BESS_3M: M1#1.23(CT9-) TB11#1.18 X17#1.6(L3_B)
CT_BESS_3P: M1#1.22(CT9+) TB11#1.17 X17#1.5(L3_W)
CT_POI_1M: M1#1.7(CT1-) TB11#1.2 X15#1.2(L1_B)
CT_POI_1P: M1#1.6(CT1+) TB11#1.1 X15#1.1(L1_W)
CT_POI_2M: M1#1.9(CT2-) TB11#1.4 X15#1.4(L2_B)
CT_POI_2P: M1#1.8(CT2+) TB11#1.3 X15#1.3(L2_W)
CT_POI_3M: M1#1.11(CT3-) TB11#1.6 X15#1.6(L3_B)
CT_POI_3P: M1#1.10(CT3+) TB11#1.5 X15#1.5(L3_W)
CT_SOL_1M: M1#1.13(CT4-) TB11#1.8 X16#1.2(L1_B)
CT_SOL_1P: M1#1.12(CT4+) TB11#1.7 X16#1.1(L1_W)
CT_SOL_2M: M1#1.15(CT5-) TB11#1.10 X16#1.4(L2_B)
CT_SOL_2P: M1#1.14(CT5+) TB11#1.9 X16#1.3(L2_W)
CT_SOL_3M: M1#1.17(CT6-) TB11#1.12 X16#1.6(L3_B)
CT_SOL_3P: M1#1.16(CT6+) TB11#1.11 X16#1.5(L3_W)
CTRL_L1: CB2#1.3 F6#1.1 F19#1.1
CTRL_L2: CB2#1.4 F7#1.1 F9#1.1
DS1_MON_A: DS1#1.7(MON_A) MM1#1.3(IN+) R10#1.1
DS1_MON_B: DS1#1.8(MON_B) MM1#1.4(IN-) R10#1.2
EPO_1A: K1#1.3(11_COM) TB23#1.1 X23#1.1(EPO_A1)
EPO_1B: K1#1.5(14_NO) TB23#1.2 X23#1.2(EPO_A2)
EPO_2A: K1#1.6(21_COM) TB23#1.3 X23#1.3(EPO_B1)
EPO_2B: K1#1.7(22_NC) TB23#1.4 X23#1.4(EPO_B2)
ETH_CPU1_LAN: CPU1#1.4(LAN) SW1#1.6(P4)
ETH_CPU1_WAN: CPU1#1.3(WAN) SW1#1.4(P2)
ETH_CPU2_LAN: CPU2#1.4(LAN) SW1#1.7(P5)
ETH_CPU2_WAN: CPU2#1.3(WAN) SW1#1.5(P3)
ETH_IO: IO1#1.10(ETH) SW1#1.9(P7)
ETH_METER: M1#1.5(ETH) SW1#1.8(P6)
ETH_MOD1: EM1#1.11(RJ45) SW1#1.13(P11)
ETH_MOD2: EM2#1.11(RJ45) SW1#1.14(P12)
ETH_MOD3: EM3#1.11(RJ45) SW1#1.15(P13)
ETH_PCS1: SW1#1.10(P8) X3#1.1(ETH)
ETH_PCS2: SW1#1.11(P9) X4#1.1(ETH)
ETH_PCS3: SW1#1.12(P10) X5#1.1(ETH)
ETH_WAN_UPLINK: SW1#1.3(P1) X2#1.1(ETH)
FACP_AC_L: CB9#1.2 FACP1#1.1(AC_L) PSN1#1.1(AC_L)
FACP_ALM: FACP1#1.20(ALM_NO) IO1#1.3(DI0)
FACP_COM: FACP1#1.21(ALM_C) FACP1#1.23(SUP_C) FACP1#1.25(TRB_C) IO1#1.6(DI.COM)
FACP_SUP: FACP1#1.22(SUP_NO) IO1#1.4(DI1)
FACP_TRB: FACP1#1.24(TRB_NO) IO1#1.5(DI2)
FT_A: F18#1.2 FACP1#1.26(TRIP_C)
FT_B: FACP1#1.27(TRIP_NO) K1#1.1(A1+)
HTR_FEED: CB11#1.2 TH1#1.1
HTR_L: HTR1#1.1(L) TH1#1.2
MAIN_L1: CB1#1.1 F1#1.1 F4#1.1 Q1#1.4
MAIN_L2: CB1#1.2 F2#1.1 F5#1.1 Q1#1.5
MAIN_L3: CB1#1.3 F3#1.1 Q1#1.6
MBMU1_C2A: EM1#1.5(J902.22) MBMU1#1.11(J5.33_TERM) R1#1.1
MBMU1_C2B: EM1#1.6(J902.21) MBMU1#1.12(J5.34_TERM) R1#1.2
MBMU2_C2A: EM2#1.5(J902.22) MBMU2#1.11(J5.33_TERM) R2#1.1
MBMU2_C2B: EM2#1.6(J902.21) MBMU2#1.12(J5.34_TERM) R2#1.2
MBMU3_C2A: EM3#1.5(J902.22) MBMU3#1.11(J5.33_TERM) R3#1.1
MBMU3_C2B: EM3#1.6(J902.21) MBMU3#1.12(J5.34_TERM) R3#1.2
MREL_N: MM2#1.4(IN-) R11#1.2 TB16#1.2 X25#1.2(MR-)
MREL_P: MM2#1.3(IN+) R11#1.1 TB16#1.1 X25#1.1(MR+)
MTR_L1: M1#1.1(L1) PT1#1.5(X1)
MTR_L2: M1#1.2(L2) PT1#1.6(X2)
MTR_L3: M1#1.3(L3) PT1#1.7(X3)
MTR_N: M1#1.4(N) PT1#1.8(XN)
NAC_N: FACP1#1.13(NAC1-) R4#1.2 SIR1#1.2(-) STB1#1.2(-)
NAC_P: FACP1#1.12(NAC1+) R4#1.1 SIR1#1.1(+) STB1#1.1(+)
PSN_TRB_A: MM3#1.3(IN+) PSN1#1.18(TRB_A) R12#1.1
PSN_TRB_B: MM3#1.4(IN-) PSN1#1.19(TRB_B) R12#1.2
PSNBAT_MID: BAT3#1.2(-) BAT4#1.1(+)
PSNBAT_N: BAT4#1.2(-) PSN1#1.5(BAT-)
PSNBAT_P: BAT3#1.1(+) PSN1#1.4(BAT+)
PSU1_L: F6#1.2 PSU1#1.1(L)
PSU2_L: F7#1.2 PSU2#1.1(L)
PSU3_L: F9#1.2 PSU3#1.1(L)
PSU4_L: F19#1.2 PSU4#1.1(L)
PSU_OK_A: IO1#1.7(DI3) RM1#1.5(OK_B)
PSU_OK_B: IO1#1.8(DI4) RM2#1.5(OK_B)
REL1_N: DS1#1.2(C1_IN-) PSN1#1.13(OUT1-)
REL1_P: DS1#1.1(C1_IN+) PSN1#1.12(OUT1+)
REL2_N: DS1#1.4(C2_IN-) PSN1#1.15(OUT2-)
REL2_P: DS1#1.3(C2_IN+) PSN1#1.14(OUT2+)
REL3_N: DS1#1.6(C3_IN-) PSN1#1.17(OUT3-)
REL3_P: DS1#1.5(C3_IN+) PSN1#1.16(OUT3+)
SEC_L1: CB2#1.1 CB9#1.1 T2#1.4(X1_L1)
SEC_L2: CB2#1.2 T2#1.6(X4_L2)
SEC_N: BD1#1.1(N) FACP1#1.2(AC_N) PSN1#1.2(AC_N) PSU1#1.2(N) PSU2#1.2(N) PSU3#1.2(N) PSU4#1.2(N) T2#1.5(XN_N)
SLC_R3N: FACP1#1.11(SLC_RET-) TB9#1.2 X14#1.2(SLC_RET-)
SLC_R3P: FACP1#1.10(SLC_RET+) TB9#1.1 X14#1.1(SLC_RET+)
SLC_S1N: FACP1#1.9(SLC_OUT-) MM1#1.2(SLC-) MM2#1.2(SLC-) MM3#1.2(SLC-) TB8#1.2 X12#1.2(SLC_IN-)
SLC_S1P: FACP1#1.8(SLC_OUT+) MM1#1.1(SLC+) MM2#1.1(SLC+) MM3#1.1(SLC+) TB8#1.1 X12#1.1(SLC_IN+)
SPD_L1: CB1#1.4 SPD1#1.1(L1)
SPD_L2: CB1#1.5 SPD1#1.2(L2)
SPD_L3: CB1#1.6 SPD1#1.3(L3)
SUP1_N: DS1#1.10(C1_OUT-) R5#1.2 TB14#1.2 X12#1.4(AER24-)
SUP1_P: DS1#1.9(C1_OUT+) R5#1.1 TB14#1.1 X12#1.3(AER24+)
SUP2_N: DS1#1.12(C2_OUT-) R6#1.2 TB14#1.4 X13#1.2(AER24-)
SUP2_P: DS1#1.11(C2_OUT+) R6#1.1 TB14#1.3 X13#1.1(AER24+)
SUP3_N: DS1#1.14(C3_OUT-) R7#1.2 TB14#1.6 X14#1.4(AER24-)
SUP3_P: DS1#1.13(C3_OUT+) R7#1.1 TB14#1.5 X14#1.3(AER24+)
TAP_L1: F1#1.2 PT1#1.1(H1)
TAP_L2: F2#1.2 PT1#1.2(H2)
TAP_L3: F3#1.2 PT1#1.3(H3)
TRIG1_N: FACP1#1.15(REL1-) PSN1#1.7(TRIG1-)
TRIG1_P: FACP1#1.14(REL1+) PSN1#1.6(TRIG1+)
TRIG2_N: FACP1#1.17(REL2-) PSN1#1.9(TRIG2-)
TRIG2_P: FACP1#1.16(REL2+) PSN1#1.8(TRIG2+)
TRIG3_N: FACP1#1.19(REL3-) PSN1#1.11(TRIG3-)
TRIG3_P: FACP1#1.18(REL3+) PSN1#1.10(TRIG3+)
UPS_BUF: IO1#1.9(DI5) UPS1#1.6(BUF_B)
NetEM1#1_3: EM1#1.3(J902.6_COMM_A) MBMU1#1.9(J5.29_COMM_A)
NetEM1#1_4: EM1#1.4(J902.5_COMM_B) MBMU1#1.10(J5.30_COMM_B)
NetEM1#1_7: EM1#1.7(J902.9) EM1#1.8(J902.12)
NetEM1#1_9: EM1#1.9(J902.10) EM1#1.10(J902.11)
NetEM2#1_3: EM2#1.3(J902.6_COMM_A) MBMU2#1.9(J5.29_COMM_A)
NetEM2#1_4: EM2#1.4(J902.5_COMM_B) MBMU2#1.10(J5.30_COMM_B)
NetEM2#1_7: EM2#1.7(J902.9) EM2#1.8(J902.12)
NetEM2#1_9: EM2#1.9(J902.10) EM2#1.10(J902.11)
NetEM3#1_3: EM3#1.3(J902.6_COMM_A) MBMU3#1.9(J5.29_COMM_A)
NetEM3#1_4: EM3#1.4(J902.5_COMM_B) MBMU3#1.10(J5.30_COMM_B)
NetEM3#1_7: EM3#1.7(J902.9) EM3#1.8(J902.12)
NetEM3#1_9: EM3#1.9(J902.10) EM3#1.10(J902.11)
NetMBMU1#1_1: MBMU1#1.1(J3.1) MBMU1#1.2(J3.17)
NetMBMU2#1_1: MBMU2#1.1(J3.1) MBMU2#1.2(J3.17)
NetMBMU3#1_1: MBMU3#1.1(J3.1) MBMU3#1.2(J3.17)

Not connected (* = marked no-connect by the designer): IO1#1 11(DO0)* 12(DO1)*; K1#1 4(12_NC)* 8(24_NO)*; MBMU1#1 5(J3.6_LOOP+)* 6(J3.23_LOOP-)*; MBMU2#1 5(J3.6_LOOP+)* 6(J3.23_LOOP-)*; MBMU3#1 5(J3.6_LOOP+)* 6(J3.23_LOOP-)*; SW1#1 16(P14)*

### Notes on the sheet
- z1Power - SUGARLAND BESS - COMPLETE PANEL SCHEMATIC - SINGLE SHEET (REV K / ARCH E) - DWG Z1SL-E-001 - PROPRIETARY: STR MEDICAL
- DWG Z1SL-E-001 REV K. REVISION HISTORY: A LABEL-STUB / B FIRST WIRED / C PAD-TX+1-SWITCH / D CATL DATA / E PINOUT RECOVERED /
  F AS-BUILT RE-VERIFIED / G ARCH-E ONE-PAGE / H OFFICIAL-DOC PIN VERIFICATION / I KEHUA CAB-375 INTEGRATED AUX (EXTERNAL PAD TX DELETED) /
  J 8 SWARM FINDINGS / K REVIEW-BOARD REMEDIATION: HARDWIRED PCS FIRE TRIP, DEDICATED FIRE BRANCH, FSS OPTION B SELECTED, 24V RESTRUCTURE,
  CLASS A SLC RACK-TO-RACK, ENCLOSURE HVAC CIRCUITS, SUPPLY-HEALTH MONITORING. DRAWN: CLAUDE (AI) / CHECKED: ___ / APPROVED (PE): ___
  WIRE COLORS: 480V RED / 380Y AUX ORANGE / 120V YELLOW / 24VDC BLUE / DC COM CYAN / ETHERNET PURPLE / CAN+MBMU PAIRS TEAL /
  FIRE+RELEASING DARK RED / PE GREEN / NEUTRAL GREY / METERING DK GREEN / CONNECTOR CRIMP JUMPERS DK GREY (AWG20, INSIDE MX34 PLUGS).
  REV K FIRE-TRIP CHAIN (R-01): FACP1 RELAY 26/27 PROGRAMMED NORMALLY-ENERGIZED > F18 (24V UPS-BACKED) > K1 COIL. ALARM, FACP FAILURE,
  OR SUPPLY LOSS DROPS K1 > X23 CONTACTS TO KEHUA EPO (BOTH SENSES PROVIDED - CONFIRM AT RFI-001). FACP ALM/SUP/TRB MONITOR CONTACTS
  PROGRAM N/C (OPEN = EVENT) SO A BROKEN CONDUCTOR ANNUNCIATES; IO1 + K1 SUPPLY IS UPS-BACKED (F16/F18 ON 24V_UPS).
  REV K FSS - OPTION B (FACP RELEASING) IS THE LIVE ARCHITECTURE: FACP TRIG1-3 > PSN-1000 (LISTED RELEASING PSU, 3A/CKT VS 1.1375A LOAD,
  OWN BAT3/4 + NFPA 72 CALC) > DS1 LOCKABLE SUPERVISED SERVICE DISCONNECT > TB14 > CABINET JX1 AEROSOL INPUT (PINS 3/4 PER MANUAL306).
  OPTION A (MBMU J3.6/23 LOOP) IS NOT WIRED - PINS CARRY NO-CONNECTS. DO NOT WIRE BOTH. EOLS R5-R7 AT THE JX1 END SUPERVISE EACH
  RELEASING CIRCUIT; ABORT (X24, CONSTANT-PRESSURE) + MANUAL RELEASE (X25) ARE FIELD STATIONS AT THE CABINET LINE-UP PER NFPA 72 23.8.5.6,
  EOLS AT THE STATION; DS1/PSN1/MAN-REL SUPERVISED VIA SLC MONITOR MODULES MM1-MM3. CONFIRM JX1 AEROSOL PIN FUNCTION AT CATL/POTTER ICD (RFI-002).
  REV K CLASS A SLC (R-11): PANEL SENDS ONE PAIR TO CAB1 (JX1_IN C/D) AND RECEIVES THE RETURN FROM CAB3 (JX2_OUT C/D). INTER-CABINET
  LEGS ARE RACK-TO-RACK FIELD WIRING; ROUTE THE RETURN LEG IN A SEPARATE RACEWAY FROM THE SEND LEG (NFPA 72 CLASS A SEPARATION).
  REV K 24VDC (R-08/R-09): RAIL A = PSU1+PSU2 > RM1 > UPS1 (EMS/NETWORK/IO/FIRE-TRIP). RAIL B = PSU3+PSU4 > RM2 (MBMU + ETH MODULES).
  SUPPLY HEALTH: RM1/RM2 DC-OK + UPS1 BUFFER CONTACTS > IO1 DI3/DI4/DI5 - FIRST FAILURE ANNUNCIATES AT THE EMS. CONTACT OPTION PER DATASHEET AT PROCUREMENT.
  FIRE ALARM BRANCH (R-02): CB9 15A 1P OFF SEC L1 FEEDS FACP1 + PSN1 AND NO OTHER LOAD (NEC 760.121(B)); RED HANDLE + LOCK-ON +
  'FIRE ALARM CIRCUIT' MARKING + OCPD LOCATION PLACARD AT FACP1. NOTE: BRANCH DERIVES FROM T2/CPT - OPENING Q1 PUTS FACP ON BATTERY.
  ENCLOSURE CLIMATE (R-03): AC1 230V ON CB10 (LOCKABLE = 440.14 DISCONNECT), HTR1 100W VIA TH1 ON CB11 - BOTH FROM 380Y AUX, NOT THE CPT.
  FINAL A/C SELECTION AT IFC FROM THE HEAT-BALANCE SHEET (SCHEDULE PKG); T2 PER-LEG VA CENSUS IN SCHEDULE PKG.
  AS-BUILT PINOUT (CARSON, COORDINATE-VERIFIED x3 CLUSTERS): MBMU J3.1-17 JUMPER, J3.2 +24V, J3.19 0V; J5.13/14 CAN+/- TO CABINET;
  J5.29/30 > J902.6/5 (PAIR A); J5.33/34 > J902.22/21 (PAIR B) WITH 60R CRIMPED AT MBMU END. 20AWG ALL CONNECTOR CRIMPS. J902 9-12 + 10-11 JUMPERS.
  WIRE SPECIFICATION (PER CATL EXTERNAL WIRING DIAGRAM + MX34JAHL CONNECTOR MANUAL + EnerOne+ R08306P05L31 SPEC):
  480V: 8AWG THHN/MTW CU (40A CKT), TAPS 14AWG, SPD LEADS 10AWG <=0.5M. AUX FIELD TO CABINETS: AWG10 ADAPTER CABLES PER CATL
  (JXH1: A/B CHILLER 3KW - CATL FIGURES CONFLICT: SPEC <=12.5A <1MS INRUSH, EW DIAGRAM 31A SURGE, '10A' RATING - RLA/MCA/MOCP AT RFI-002;
  CB3/5/7 = 20A C-CURVE (REV J): HOLDS 13.6A CONT + EITHER INRUSH FIGURE; NEC 440.22(A) CEILING 175% X RLA - VALID FOR RLA >= 11.5A, CONFIRM AT RFI-002.
  PANEL AUX: 10AWG HVAC (REV J) / 14AWG BMS (TRANSITION TO CATL AWG10 ADAPTER AT TB2-TB4). AUX FEEDER: 240.21(B)(2) 25-FT TAP, AMPACITY >= 1/3
  OF THE KEHUA OUTPUT BREAKER, TERMINATES IN Q2 = SINGLE OCPD; ANY KEHUA BREAKER > 30A REQUIRES FEEDER UPSIZE FROM AWG10 (RFI-001).
  MBMU+ETH RUN ON 24VDC FROM THIS PANEL; RACK-INTERNAL BMS (SBMU/CSC) ON 220V AUX VIA IN-RACK ACDC; CHILLER DIRECT 220V AUX.
  120/240V CTRL: 14AWG MTW. 24VDC: 16AWG MTW. CAN: 0.5MM2/AWG20 TWISTED-PAIR SHIELDED, TWIST PITCH 20-30MM, SINGLE-POINT GROUND,
  <=30M MBMU-TO-120R-END-TERMINAL (ELSE CANBRIDGE); CANH=YELLOW CANL=GREEN; SHIELD CRIMP M34S75C4F3, SIGNAL CRIMPS M34S75C4F2 (JAE MX34 SOP (REV K R-44)).
  ETHERNET ETH-TO-EMS/SWITCH: CAT6A MIN (CATL CHECKLIST CITES CAT7), SHIELDED; ETH MODULE HOUSING BONDED TO PE (CATL CHECK).
  FIRE: FPL 14-18AWG PER POTTER/NFPA72; RELEASING CIRCUITS FPL 14AWG. CT LEADS: 18AWG TWISTED. PE: 8AWG CU MIN, EGC PER 250.122;
  RACK GROUND >=50MM2 CU, M8 @ 10N.M (FIELD, BY OTHERS). HARNESS COLORS PER CATL: +24 RED / 0V BLACK / L RED / N BLACK / OTHERS WHITE.
  TB TYPES: SLC/SUP/CAN-SIGNAL/CT TERMINALS = INSULATED FEED-THROUGH (PHOENIX UK 5 N / UT 4) - NOT USLKG GROUND BLOCKS;
  USLKG (RAIL-BONDED) ONLY AT THE 3 CAN SHIELD POLES = SINGLE-POINT SHIELD GROUND (SB1-3). TB11 CT LANDING = UT 4 FEED-THROUGH, 18 POLES.
  R1-R3 60R (CARSON AS-BUILT): AT COMMISSIONING MEASURE J902.21/22: EXPECT ~60R; IF ~30R, REMOVE CRIMPED 60R (OVER-TERMINATION). ICD ITEM.
  AUX SOURCE: KEHUA CABINET-375 INTEGRATED 30KVA 480/380Y TX + 3 OUTPUT BREAKERS (REV I). EXACTLY ONE N-G BOND PER SEPARATELY DERIVED
  SYSTEM: BD1 AT THE CPT (IN PANEL); THE 380Y AUX SYSTEM BONDS AT THE KEHUA TX INSIDE THE PCS CABINET (CONFIRM AT RFI-001) - NEVER BOTH ENDS.
  TWO SOURCES OF SUPPLY (480V Q1 + 380Y KEHUA Q2) - NEC 409.110 WARNING LABEL; FULL LABEL SCHEDULE IN SCHEDULE PKG (409.110/409.22(B)/110.16/ESS).
  OPEN ITEMS AT IFC: PE STAMP; SCCR (UL508A SB4, SCHEDULE PKG WORKSHEET); RFI-001 KEHUA / RFI-002 CATL-POTTER ANSWERS; NFPA 72 SECONDARY
  CALC SIGN-OFF (WORKSHEET NFPA72-W1: 4.73AH FACP + PSN SEPARATE; CATL 2H SOUND/LIGHT TERM WITH AHJ); BATTALION VLAN; CLIENT DEVIATIONS
  (SINGLE EG4115 METER / SINGLE MANAGED SWITCH); WIRE NUMBERS AT FAB RELEASE. PROPRIETARY - STR MEDICAL. FOR REVIEW ONLY - PE REVIEW REQUIRED.
- z1Power - Sugarland BESS - COMPLETE PANEL SCHEMATIC - REV K - DWG Z1SL-ALT-001
- STR Medical  /  PROPRIETARY - STR MEDICAL
- FOR REVIEW ONLY - NOT FOR CONSTRUCTION - PE REVIEW REQUIRED
- Generated from the verified Rev K design database (174-net golden diff PASS)  /  2026-08-09

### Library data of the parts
AC1#1 = ENCL_AC_230V: Enclosure A/C, 230V, ~1500 BTU/h [final per heat balance]; Manufacturer: Pfannenberg/nVent; PartNumber: DTS 3141 230V class [SELECT AT IFC]
BAT1#1 BAT2#1 = BATT_12V: Battery 12V 8Ah SLA (FACP); Manufacturer: Power-Sonic; PartNumber: PS-1280
BAT3#1 BAT4#1 = BATT_12V: Battery 12V 8Ah SLA (PSN1, REV K); Manufacturer: Power-Sonic; PartNumber: PS-1280
BD1#1 = BOND_JUMPER: N-G bond kit #8 AWG Cu + lugs + label; Manufacturer: Ilsco; PartNumber: [kit per shop practice]
CB1#1 = CB_3P: SPD breaker 30A 3P UL489 DIN, 480Y/277V, 10kA min; Manufacturer: ABB; PartNumber: SU203M-K30 [PROPOSED - CONFIRM AT PROCUREMENT]
CB2#1 = CB_2P: Control main breaker 2P 15A UL489 DIN, 240V, 10kA; Manufacturer: ABB; PartNumber: SU202M-C15 [PROPOSED]
CB3#1 CB5#1 CB7#1 = CB_1P: Branch breaker 20A 1P UL489, C-curve, 480Y/277V, 10kA; Manufacturer: ABB; PartNumber: SU201M-C20 [PROPOSED - REV K R-04]
CB4#1 CB6#1 CB8#1 = CB_1P: Branch breaker 6A 1P UL489, C-curve, 480Y/277V, 10kA; Manufacturer: ABB; PartNumber: SU201M-C6 [PROPOSED - REV K R-04]
CB9#1 = CB_1P: FIRE ALARM branch breaker 1P 15A UL489, RED handle + lock-on; Manufacturer: ABB; PartNumber: SU201M-C15 + S2C-H6R red + MSL-2 lock [PROPOSED]
CB10#1 = CB_1P: Enclosure A/C breaker 10A 1P UL489, 480Y/277V, lockable; Manufacturer: ABB; PartNumber: SU201M-C10 + MSL-2 [PROPOSED]
CB11#1 = CB_1P: Enclosure heater breaker 6A 1P UL489, 480Y/277V; Manufacturer: ABB; PartNumber: SU201M-C6 [PROPOSED]
CPU1#1 CPU2#1 = MOXA_UC2222A: EMS computer, Arm DIN-rail, Linux (Battalion image); Manufacturer: Moxa; PartNumber: UC-2222A-T-US
DS1#1 = REL_SERVICE_DISC: Releasing service disconnect, 3-ckt, lockable, position-supervised; Manufacturer: Potter/equal; PartNumber: [CONFIRM LISTED DEVICE AT ICD]
EM1#1 EM2#1 EM3#1 = CATL_ETH_ASBUILT: ETH comms module
F1#1 F2#1 F3#1 = FUSE_KLKR: Fuse, Class CC fast-acting 1A (meter taps); Manufacturer: Littelfuse; PartNumber: KLKR-1
F4#1 F5#1 = FUSE_KLKR: Fuse, Class CC TIME-DELAY 3A (CPT primary, 450.3(B) <=3A); Manufacturer: Littelfuse; PartNumber: FNQ-R-3
F6#1 F7#1 = FUSE_KLKR: Fuse, Class CC time-delay 4A (PSU1/PSU2 primaries); Manufacturer: Littelfuse
F9#1 F19#1 = FUSE_KLKR: Fuse, Class CC time-delay 6A (PSU3/PSU4 primaries); Manufacturer: Littelfuse
F10#1 F11#1 F12#1 F13#1 F14#1 F15#1 F16#1 F17#1 F18#1 = FUSE_KLKR: Fuse, Class CC: KLKR-2 x7 (CPU1/2, BMS1-3, IO, ETH), KLKR-3 x1 (network), KLKR-1 x1 (fire trip loop); Manufacturer: Littelfuse; PartNumber: KLKR-1/-2/-3 per schedule
FACP1#1 = POTTER_ARC100: Addressable releasing FACP, 100-pt; Manufacturer: Potter
GB1#1 = PE_GROUND_BUS: Ground bus bar kit + lugs; Manufacturer: Ilsco/Panduit; PartNumber: IGB-14 class [PROPOSED]
HTR1#1 = ENCL_HEATER: Anti-condensation heater 100W + NC thermostat; Manufacturer: Stego; PartNumber: HGL 046 + KTO 011 [PROPOSED]
IO1#1 = IOLOGIK_E1214: Remote I/O, 6 DI / 6 relay DO, Ethernet; Manufacturer: Moxa
K1#1 = RELAY_2FORMC_24V: Interposing relay, 2 Form C, 24VDC coil, DIN (PCS fire trip); Manufacturer: Phoenix Contact; PartNumber: RIF-1-RPT-LDP-24DC [PROPOSED]
M1#1 = EGAUGE_EG4115: Revenue meter, 15 CT inputs, Ethernet; PartNumber: EG4115 (Core)
MBMU1#1 MBMU2#1 MBMU3#1 = CATL_MBMU_ASBUILT: Master BMS unit
MM1#1 MM2#1 MM3#1 = SLC_MONITOR_MOD: SLC monitor module (DS1 position / PSN trouble / manual release); Manufacturer: Potter; PartNumber: PAD100-IM [CONFIRM]
PSN1#1 = POTTER_PSN1000: Listed releasing/aux power supply 10A (3A/ckt); Manufacturer: Potter
PSU1#1 PSU2#1 = NDR75_24: PSU 24VDC 75W DIN (rail A); Manufacturer: Mean Well
PSU3#1 PSU4#1 = NDR75_24: PSU 24VDC 240W/10A DIN (rail B, REV K R-08: now REDUNDANT pair); Manufacturer: Mean Well
PT1#1 = PT_3PH: Potential transformer set, 480:120, metering class; Manufacturer: Functional Devices/ITI; PartNumber: [VERIFY ratio per Carson]
Q1#1 = DISC_3P_40A: Main disconnect breaker 40A 3P UL489 DIN, 480V, marked IR; Manufacturer: Phoenix Contact; PartNumber: TMC S3D (per Carson) [VERIFY AIC vs SCCR study]
Q2#1 = DISC_3P_40A: Aux main breaker 25A 3P, 480Y/277V UL489, marked IR; Manufacturer: ABB; PartNumber: SU203M-C25 [PROPOSED]
R1#1 R2#1 R3#1 = RESISTOR: Termination resistor 60R 0.25W - crimped into MBMU J5.33/34
R4#1 R5#1 R6#1 R7#1 R8#1 R10#1 R11#1 R12#1 = RESISTOR_L: EOL devices: NAC(R4), SUP1-3(R5-7), abort(R8), MM inputs(R10,R12), man-rel(R11); Manufacturer: Potter; PartNumber: EOLD 3005012
RM1#1 = DRDN20_24_OK: Redundancy module 20A + DC-OK contact; Manufacturer: Mean Well; PartNumber: DRDN20-24 [CONFIRM DC-OK contact option]
RM2#1 = DRDN20_24_OK: Redundancy module 40A + DC-OK contact (REV K); Manufacturer: Mean Well; PartNumber: DRDN40-24 [CONFIRM DC-OK contact option]
SB1#1 SB2#1 SB3#1 = BOND_JUMPER: TB, USLKG 5 ground block - CAN SHIELD POLES ONLY; Manufacturer: Phoenix Contact; PartNumber: USLKG 5
SIR1#1 = SIREN: Siren, 24VDC, panel mount; Manufacturer: Potter; PartNumber: SQ-24 class [PROPOSED]
SPD1#1 = SPD_T2_480Y277: Type 2 SPD, 480/277Y, NEMA panel mount; Manufacturer: Raycap/Eaton; PartNumber: [VERIFY P/N + In/AIC]
STB1#1 = STROBE_HT8AEHA: Strobe/horn; Manufacturer: Eaton; PartNumber: HT8AEHA (per Carson)
SW1#1 = EDS4014_MANAGED: Managed switch 14-port, VLAN, DIN; Manufacturer: Moxa; PartNumber: EDS-4014 [VERIFY variant w/ Battalion]
T2#1 = CPT_480_120240: Control power TX 500VA 480>120/240, encapsulated; Manufacturer: SolaHD/HPS; PartNumber: E500 class [VERIFY]
TB1#1 TB13#1 = TB_5: Feed-through TB, UT 6 (grey) + UT 6-PE (gn/ye); Manufacturer: Phoenix Contact; PartNumber: UT 6 / UT 6-PE
TB2#1 TB3#1 TB4#1 = TB_5L: Feed-through TB, UT 6 + UT 6-PE, cabinet aux circuits; Manufacturer: Phoenix Contact; PartNumber: UT 6 / UT 6-PE
TB5#1 TB6#1 TB7#1 = TB_3L: TB, UK 5 N insulated feed-through (CAN H/L); Manufacturer: Phoenix Contact; PartNumber: UK 5 N
TB8#1 TB9#1 TB15#1 TB16#1 = TB_2L: TB, UK 5 N insulated feed-through (SLC send/return, suppression, abort, man-rel, EPO); Manufacturer: Phoenix Contact; PartNumber: UK 5 N
TB11#1 = TB_18L: TB, UT 4 feed-through (CT landing, 18 pos + spares); Manufacturer: Phoenix Contact; PartNumber: UT 4
TB14#1 = TB_6L: TB, UK 5 N insulated feed-through (SLC send/return, suppression, abort, man-rel, EPO); Manufacturer: Phoenix Contact; PartNumber: UK 5 N
TB23#1 = TB_4L: TB, UK 5 N insulated feed-through (SLC send/return, suppression, abort, man-rel, EPO); Manufacturer: Phoenix Contact; PartNumber: UK 5 N
TH1#1 = THERMOSTAT_NC: Anti-condensation heater 100W + NC thermostat; Manufacturer: Stego; PartNumber: HGL 046 + KTO 011 [PROPOSED]
UPS1#1 = QUINTCAP_4KJ: DC UPS supercap 4kJ 24VDC + signaling contact; Manufacturer: Phoenix Contact; PartNumber: QUINT4-CAP/24DC/5/4KJ
X1#1 = FIELD_480V_SOURCE
X2#1 X3#1 X4#1 X5#1 = FIELD_ETH_DEV
X6#1 X7#1 X8#1 = FIELD_CATL_AUX
X9#1 X10#1 X11#1 = FIELD_CATL_CAN
X12#1 = FIELD_CATL_SLC_IN
X13#1 = FIELD_CATL_SUPONLY
X14#1 = FIELD_CATL_SLC_OUT
X15#1 X16#1 X17#1 = FIELD_CT_SET: Split-core CT, 333mV UL2808 (PoI/Solar/BESS L1-L3, field sets); Manufacturer: eGauge; PartNumber: ECS series [size per conductor]
X18#1 = KEHUA_AUX_SRC: Aux 380Y/220V source = Kehua PCS Cabinet-375 internal 30kVA 480/380 TX + 3 output breakers
X23#1 = FIELD_KEHUA_EPO
X24#1 = FIELD_ABORT_STN: Abort station, constant-pressure, guarded (FIELD at cabinet line-up); Manufacturer: Potter; PartNumber: APS-1 class [CONFIRM AT ICD]
X25#1 = FIELD_MANREL_STN: Manual release station, dual-action (FIELD); Manufacturer: Potter; PartNumber: RMS-1T class [CONFIRM AT ICD]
